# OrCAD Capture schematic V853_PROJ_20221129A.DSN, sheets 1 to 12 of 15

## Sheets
1 01 REVISION HISTORY: title: V853_PRO; rev: V1.0; company: 1; note: Block; note: 1; note: 1
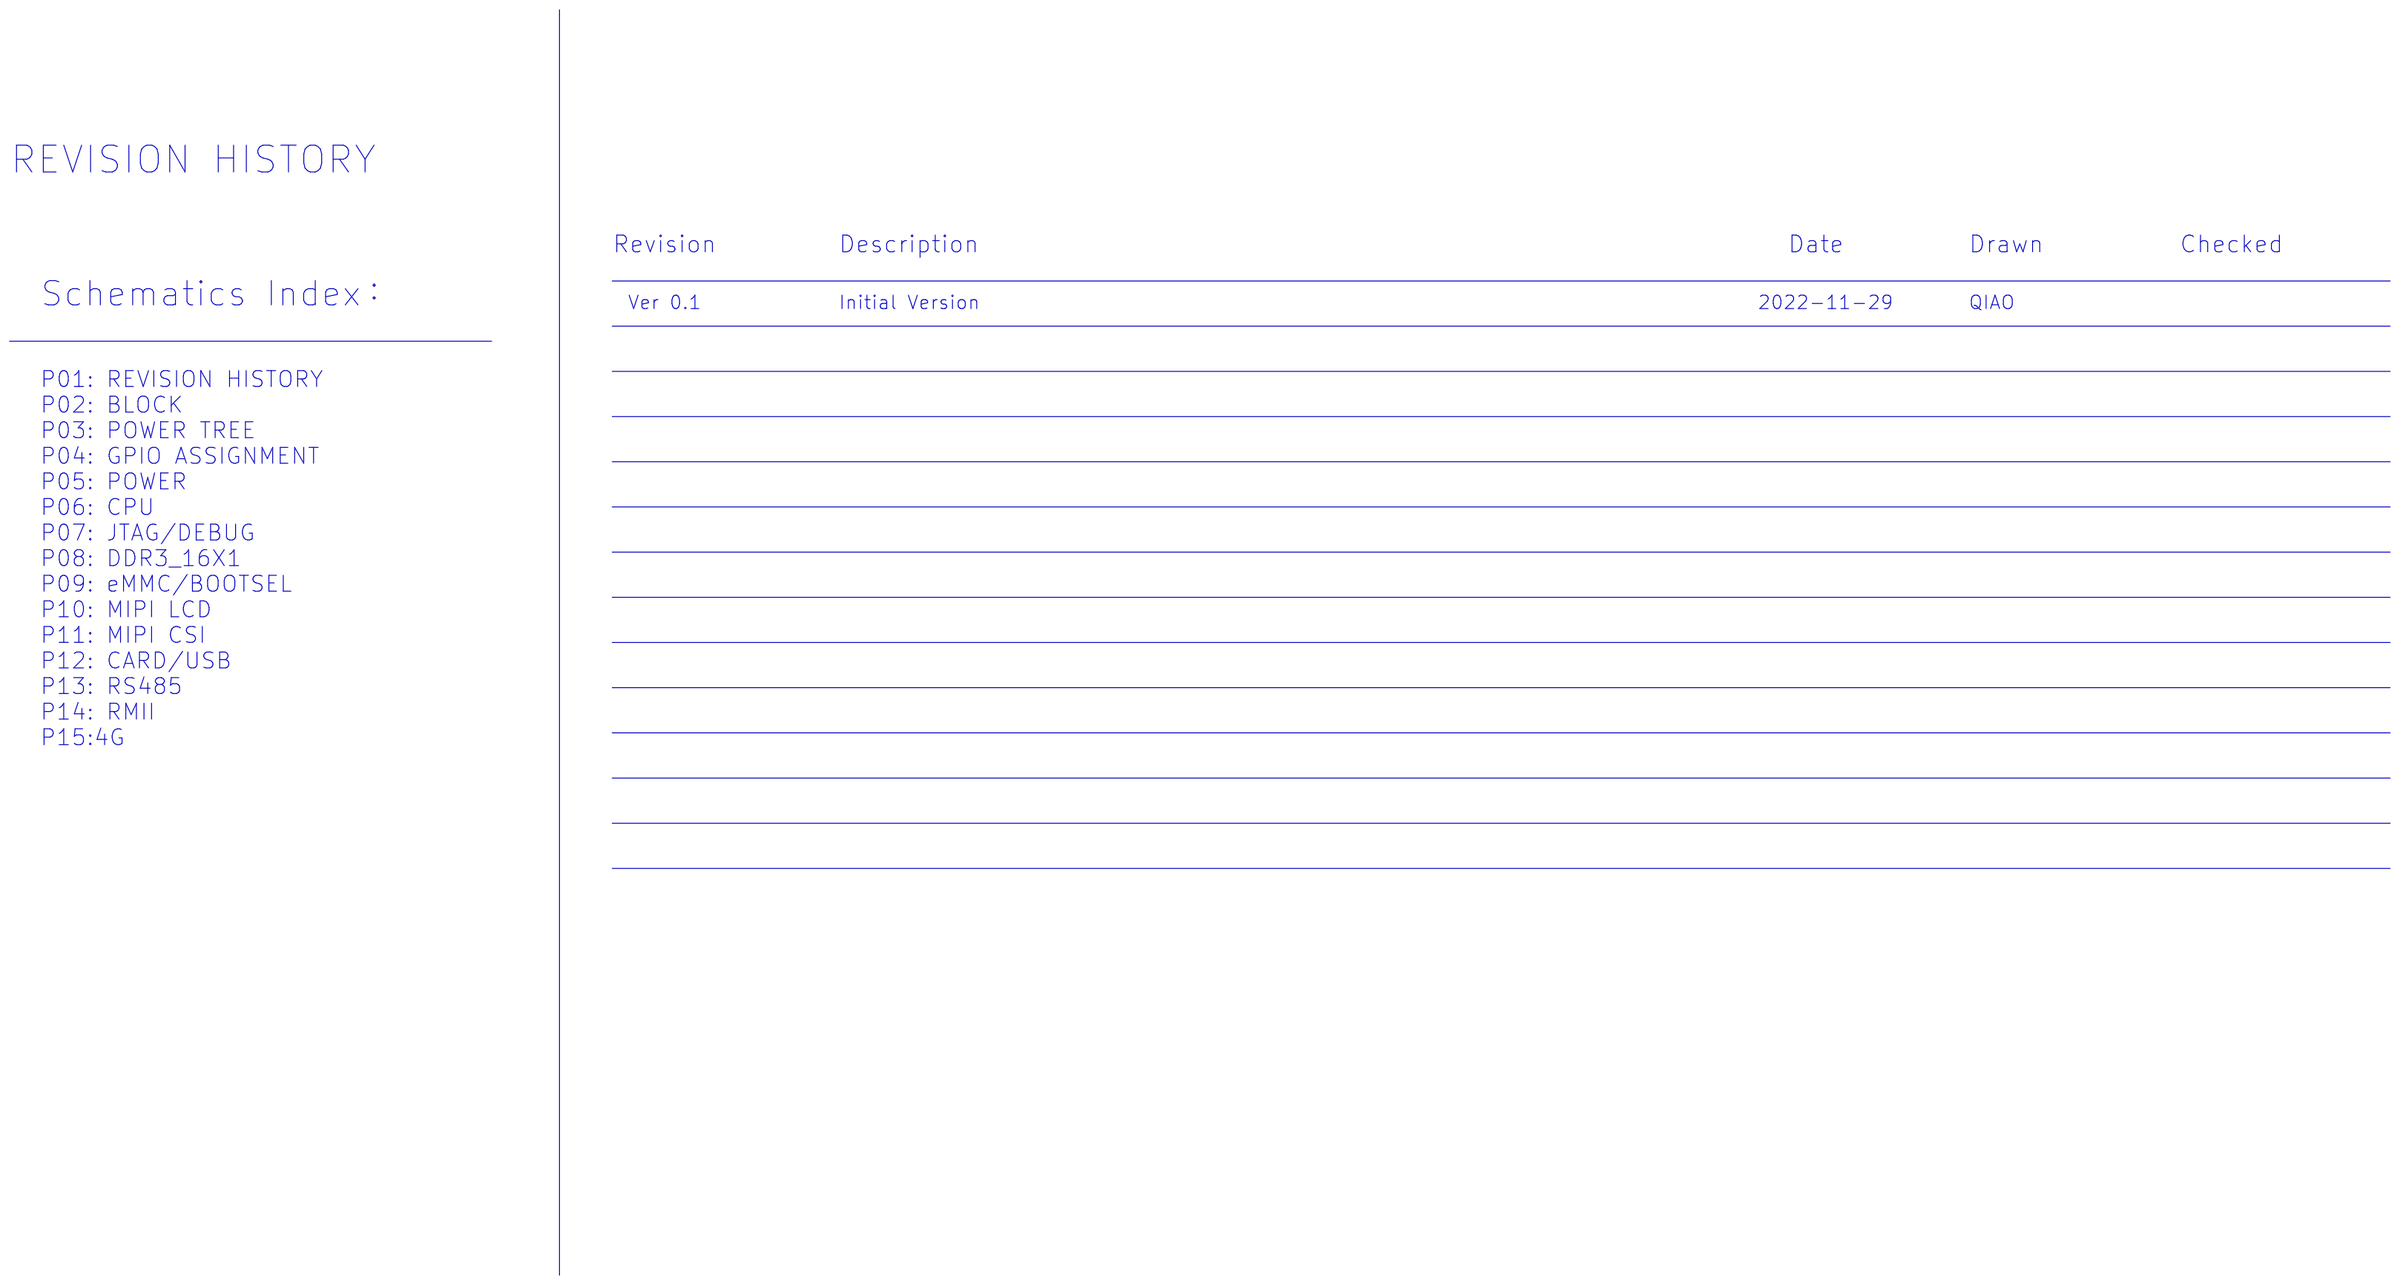
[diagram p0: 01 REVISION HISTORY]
2 02 BLOCK
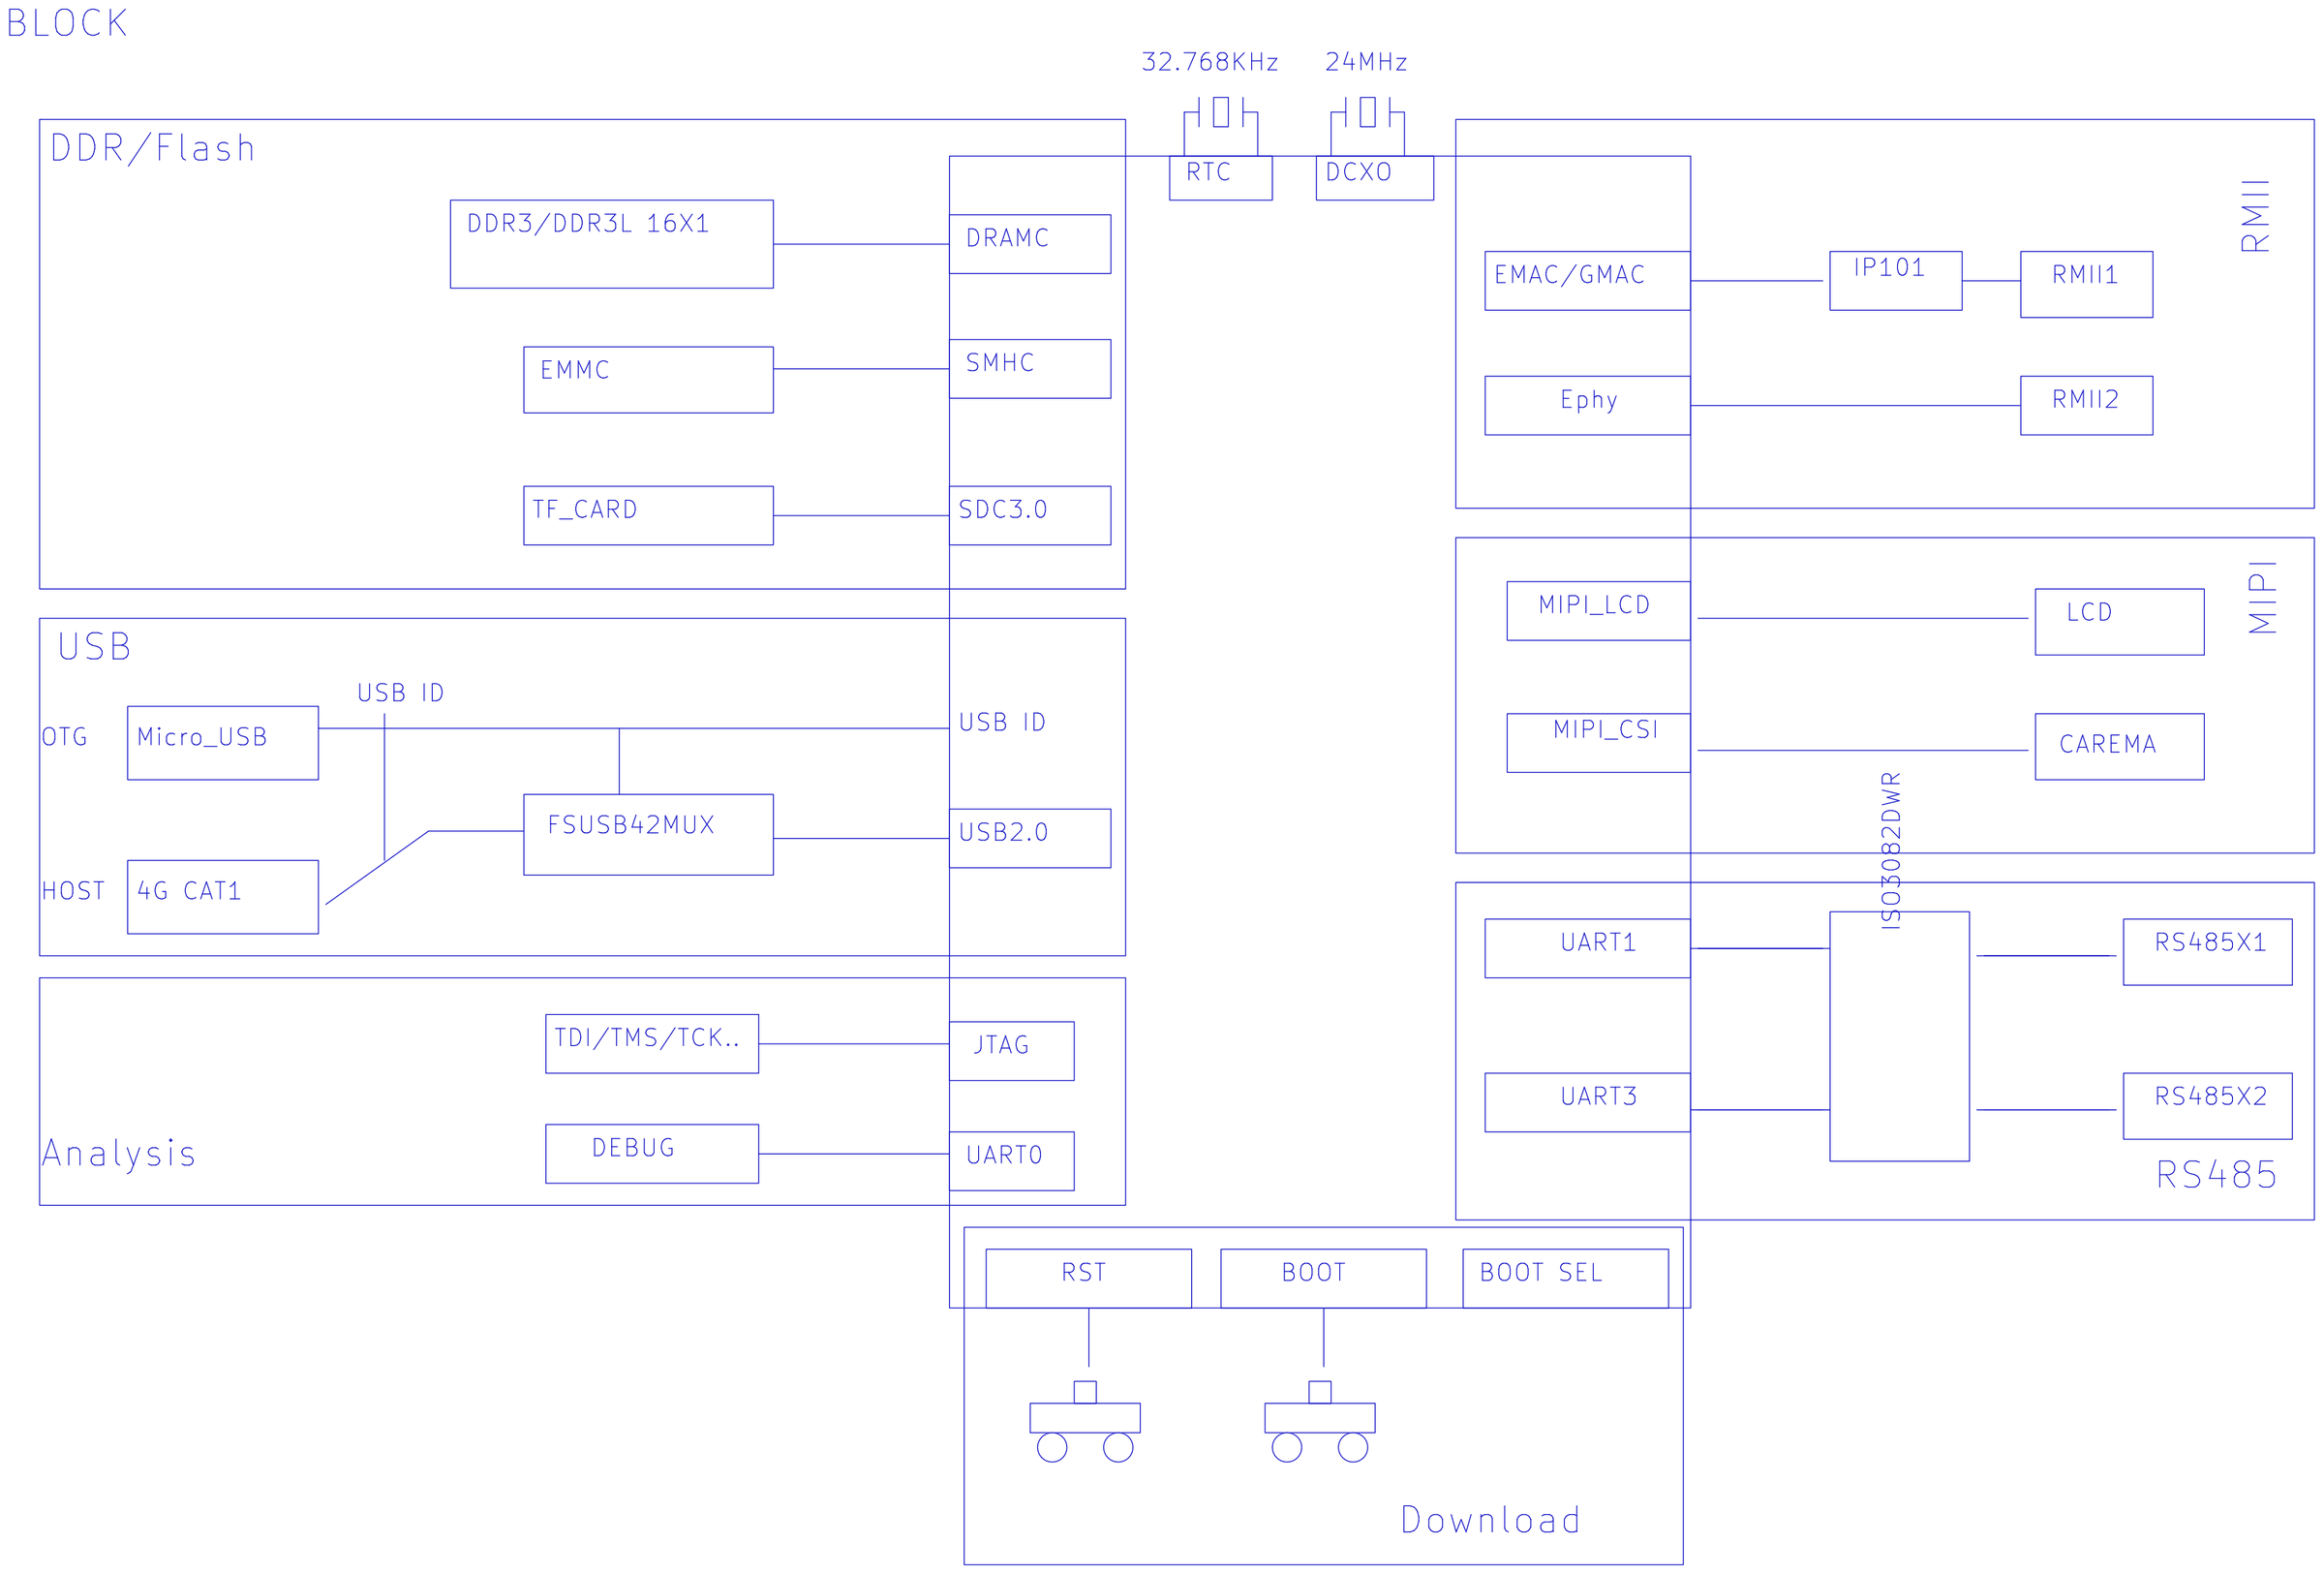
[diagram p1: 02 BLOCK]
3 03 POWER TREE: note: PWR TREE
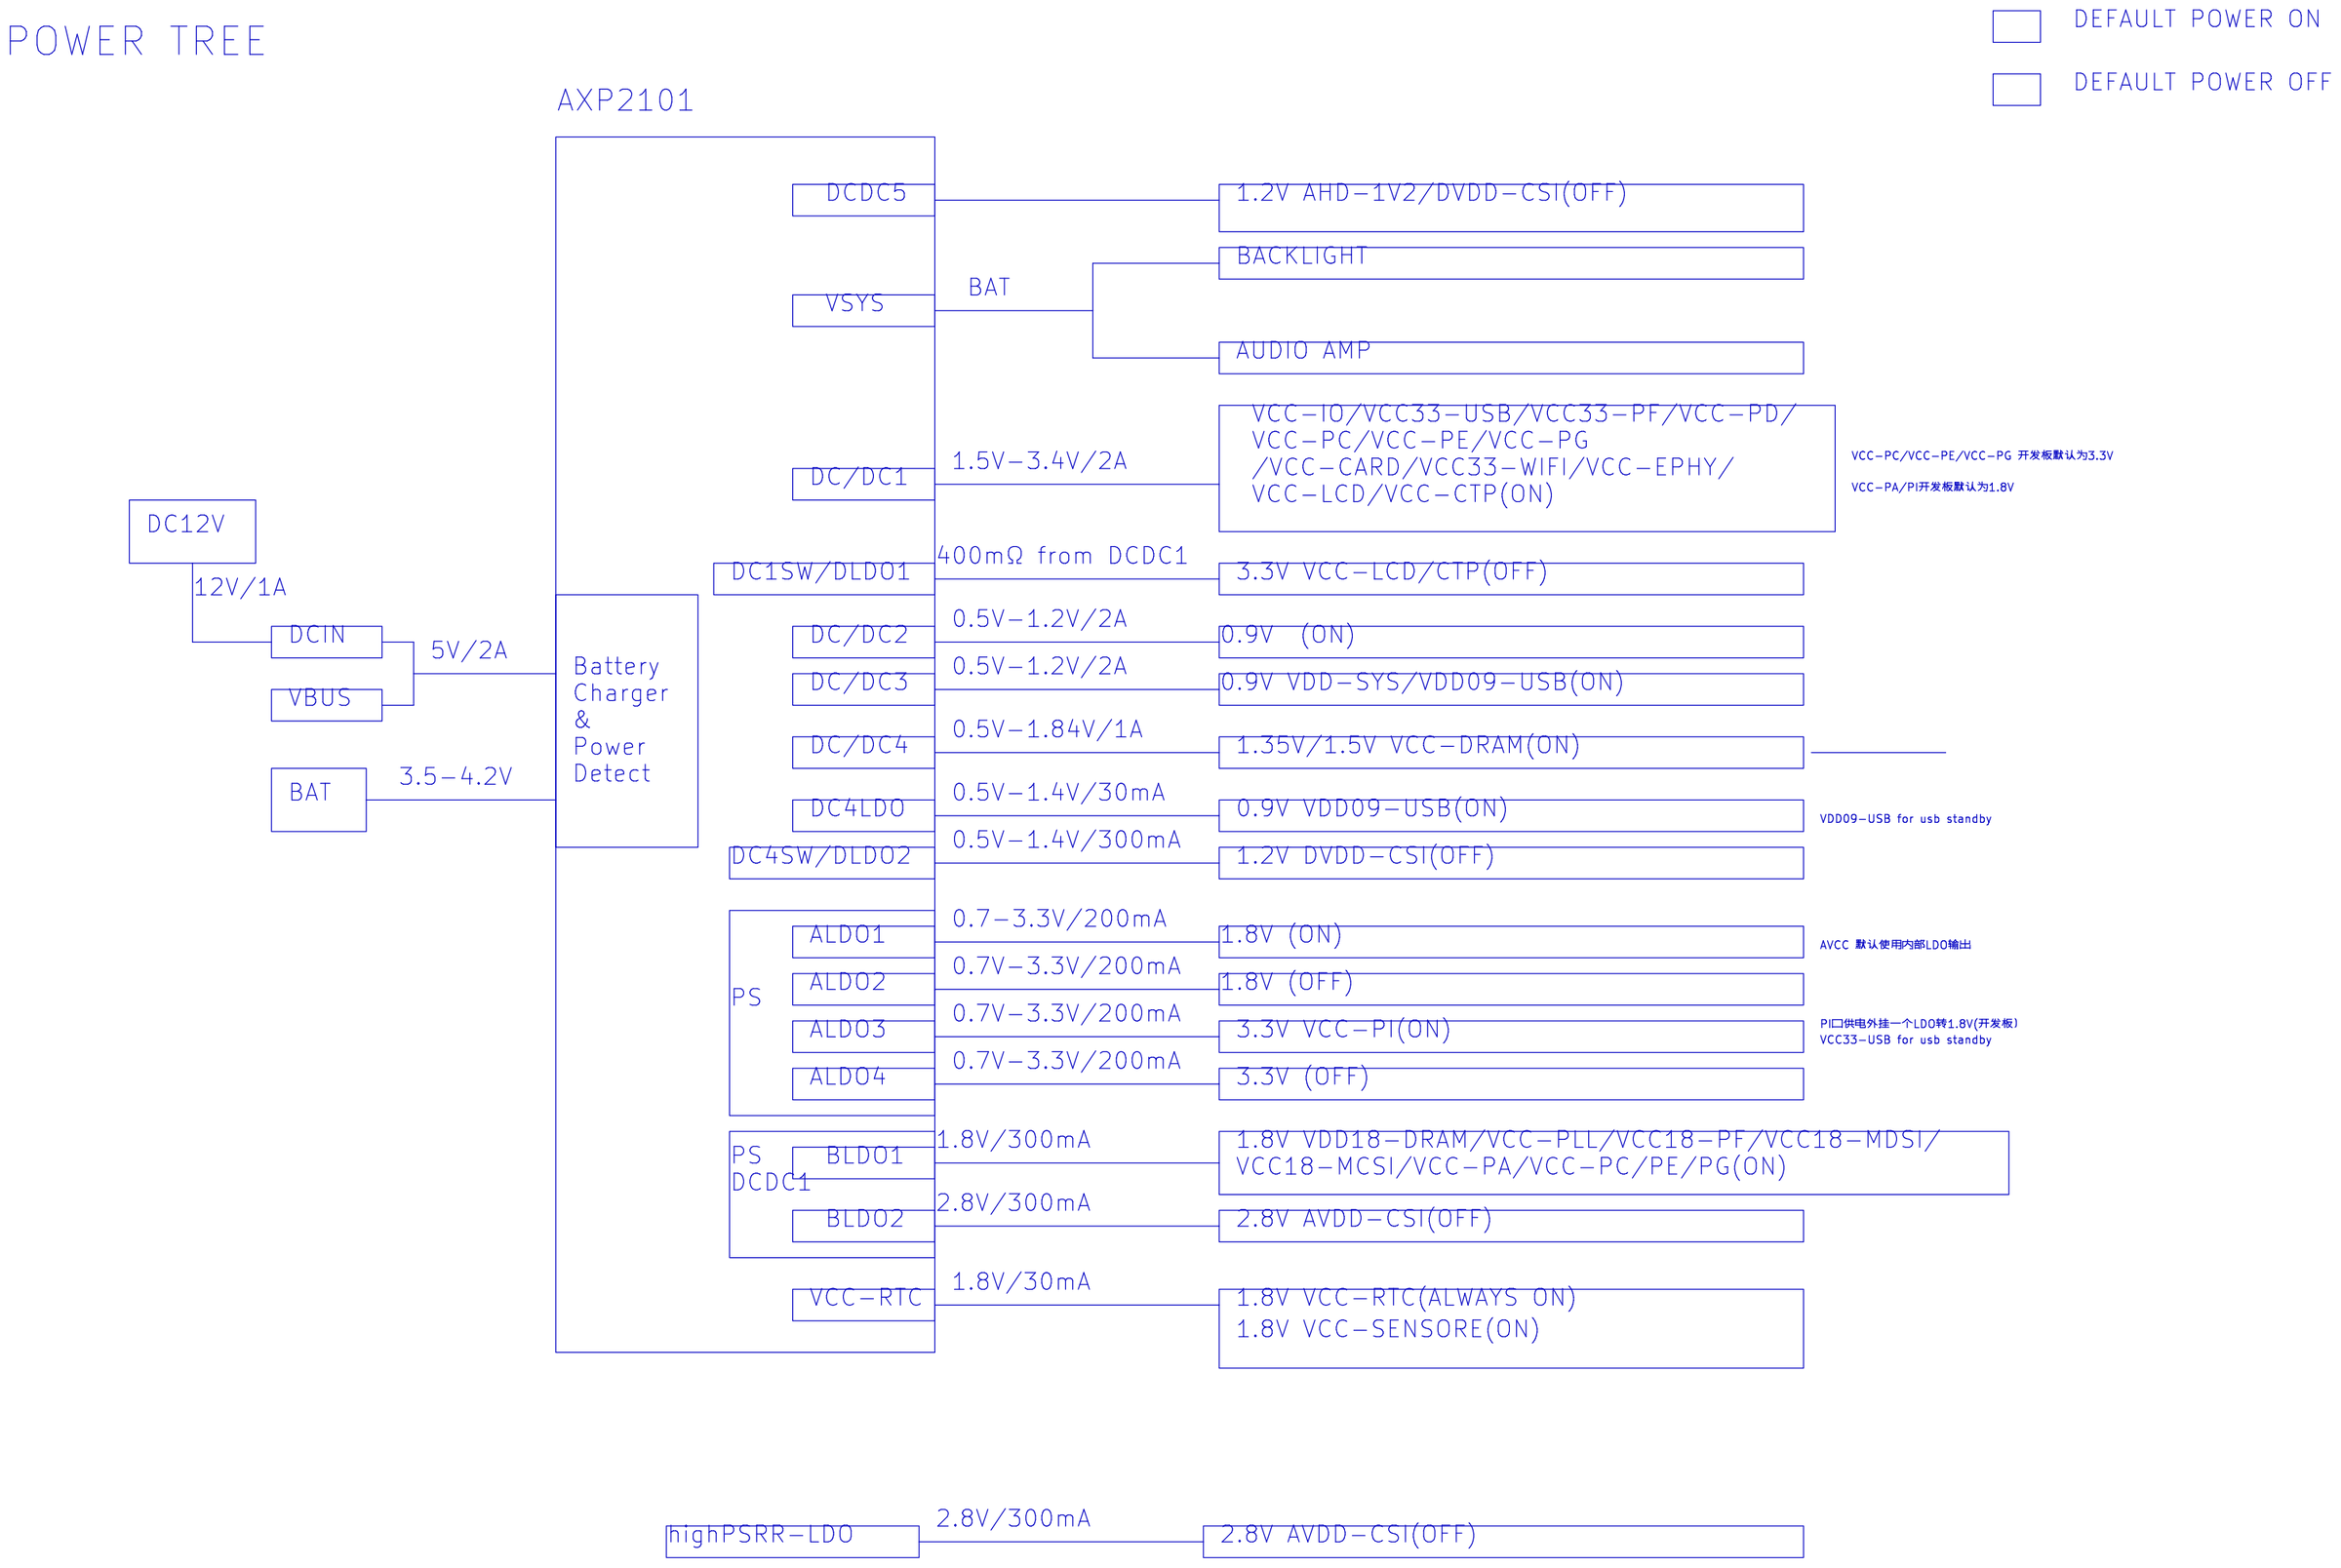
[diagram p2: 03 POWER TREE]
4 04 GPIO ASSIGNMENT: note: GPIO_CTRL
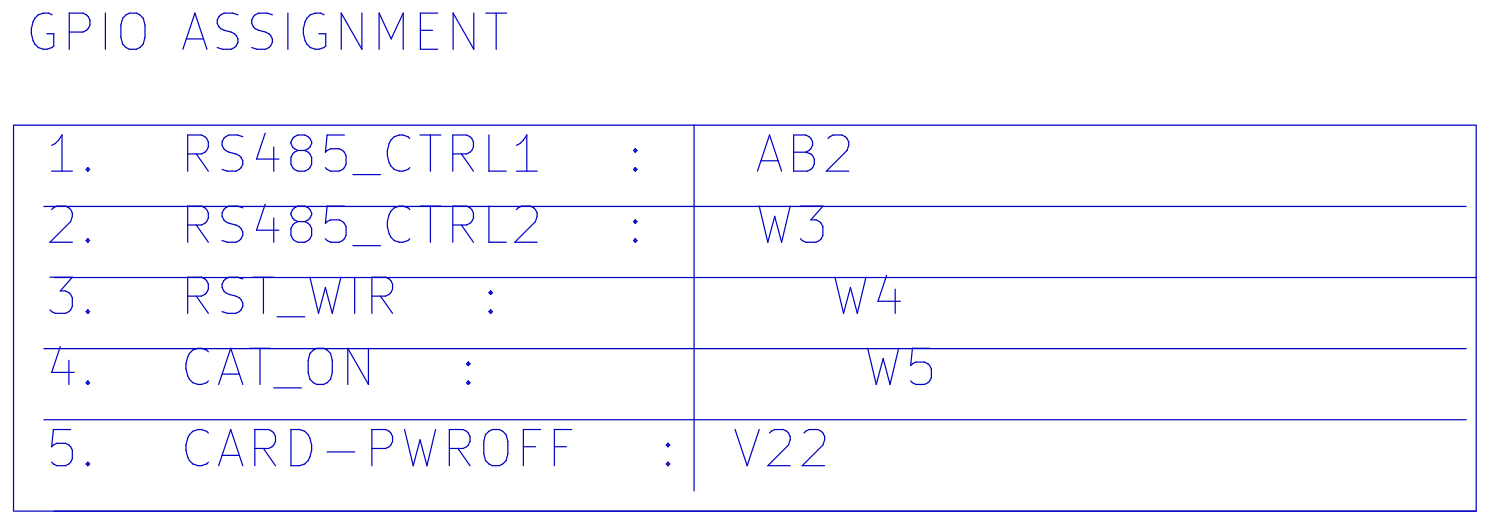
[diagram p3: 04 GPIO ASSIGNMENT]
5 05 POWER: size A2; note: PWR
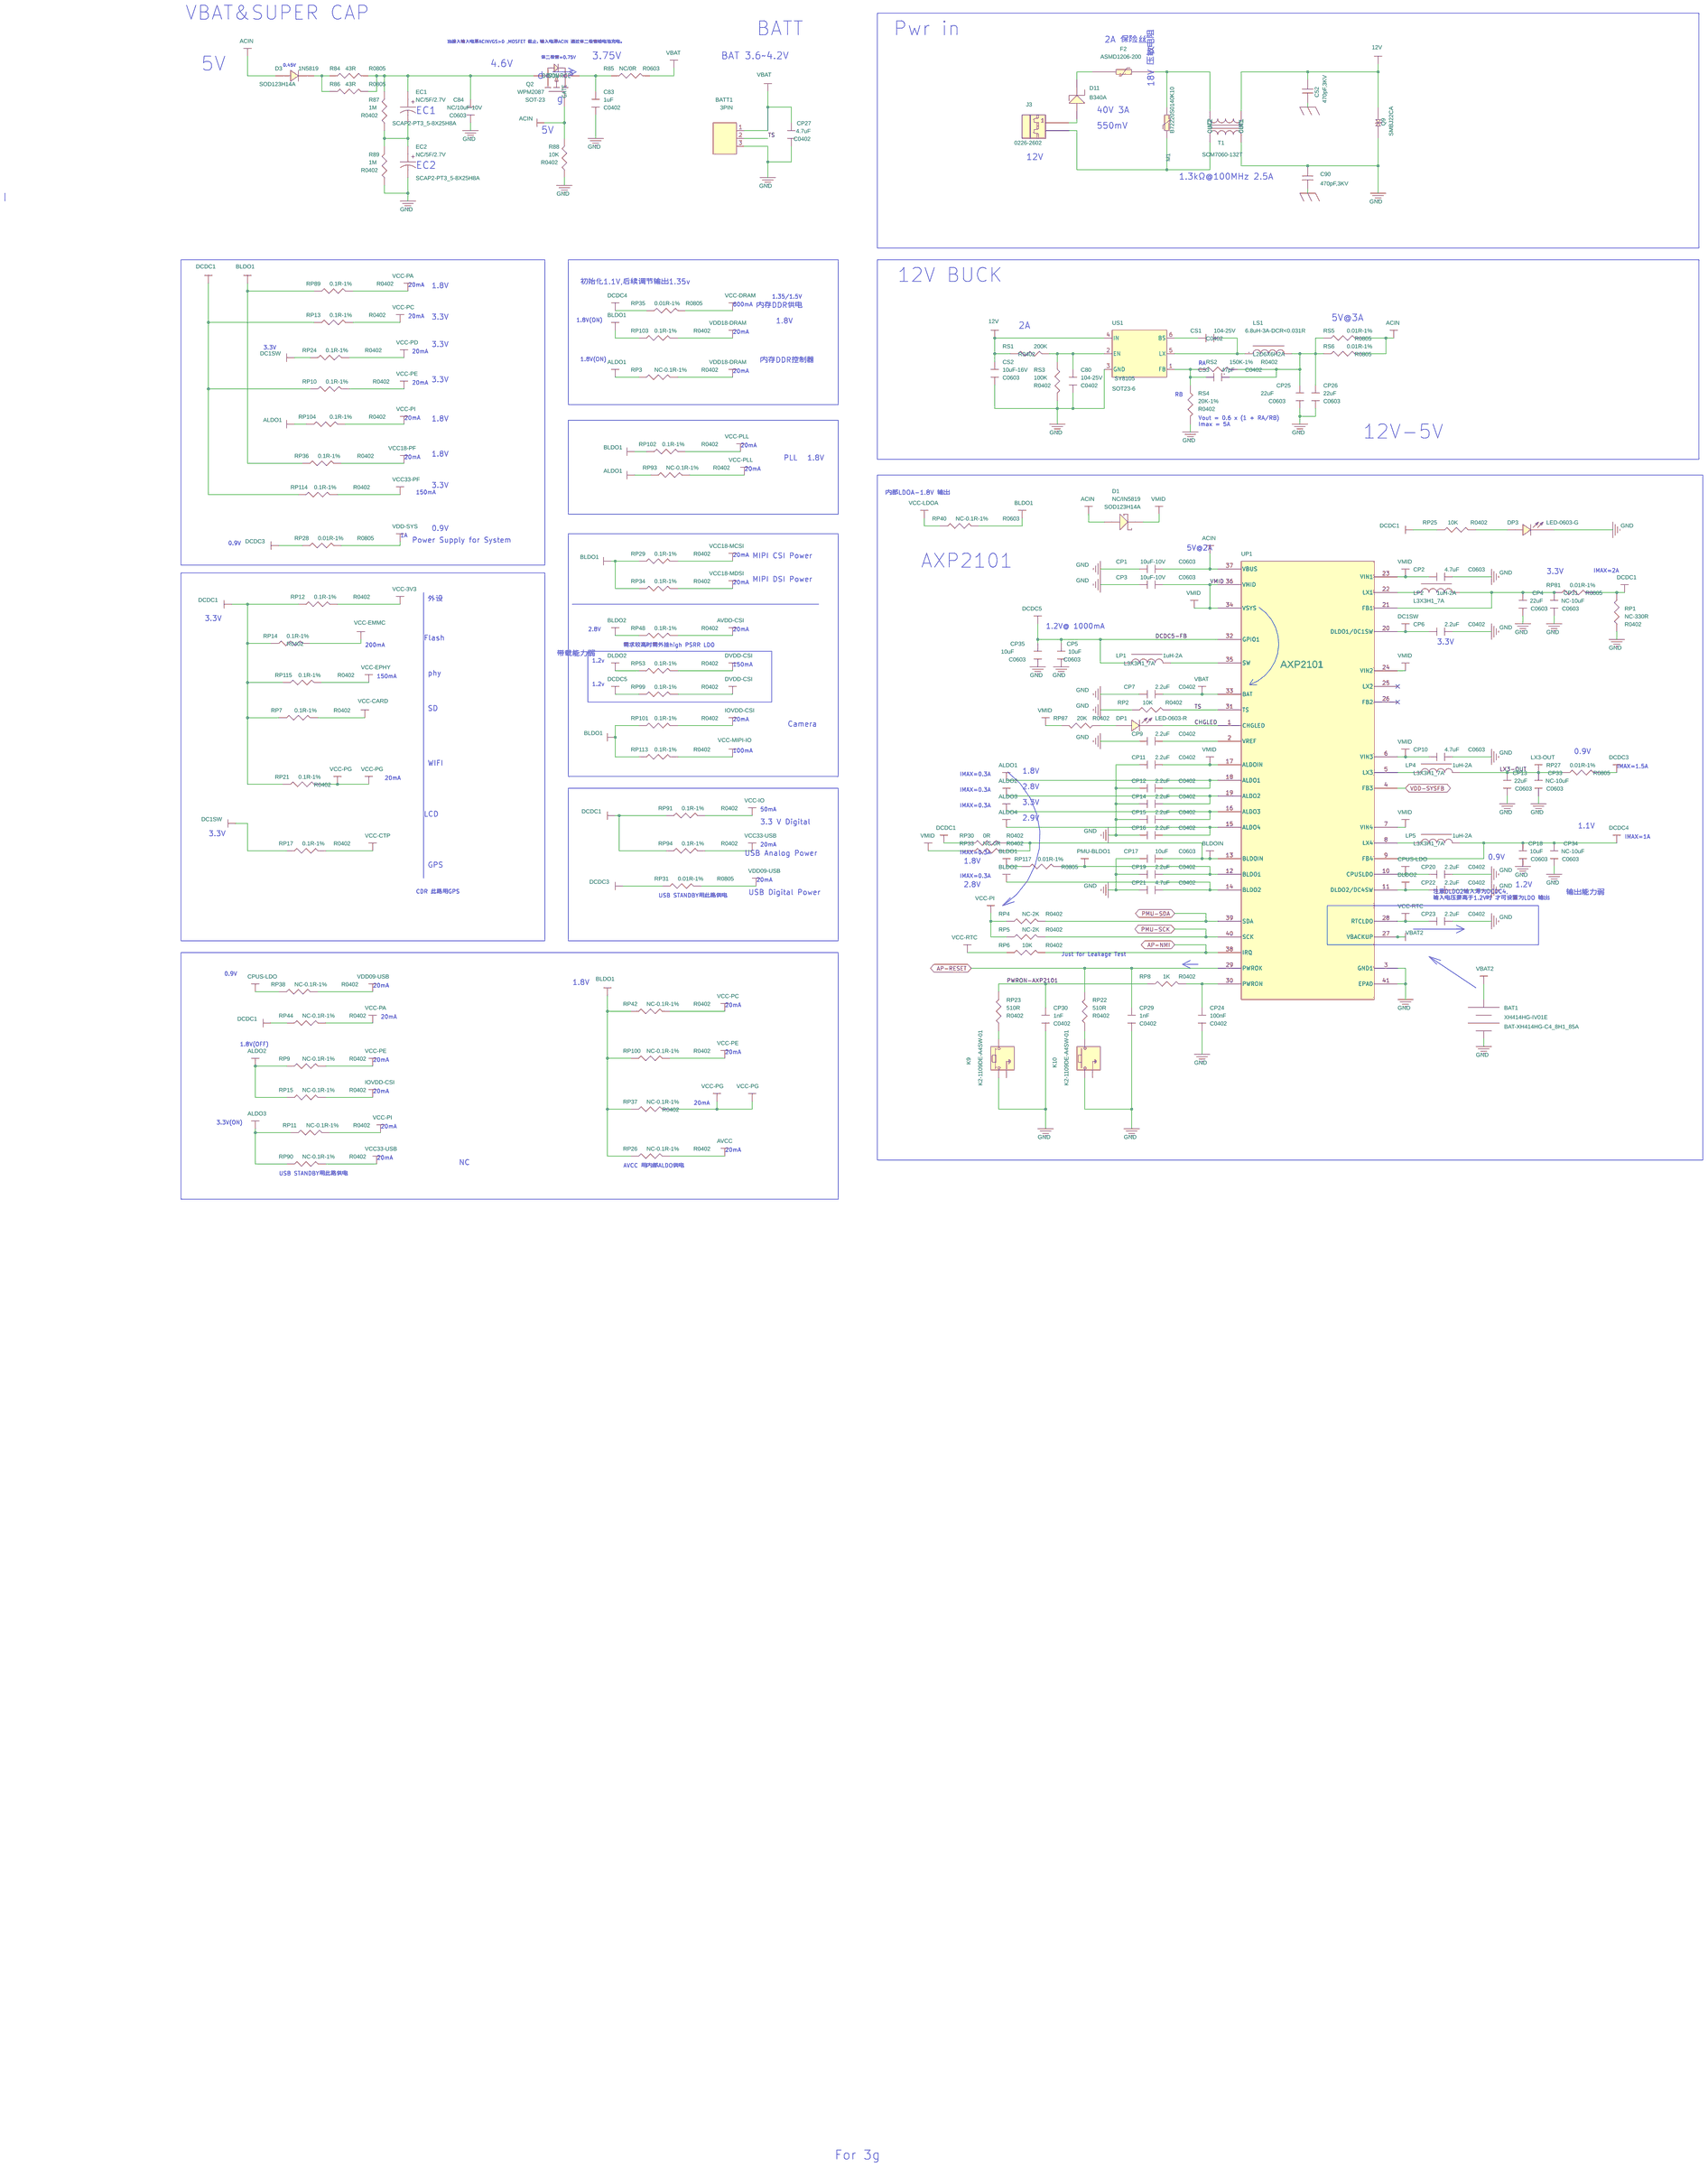
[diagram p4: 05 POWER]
6 06 CPU: size A3; note: MPU
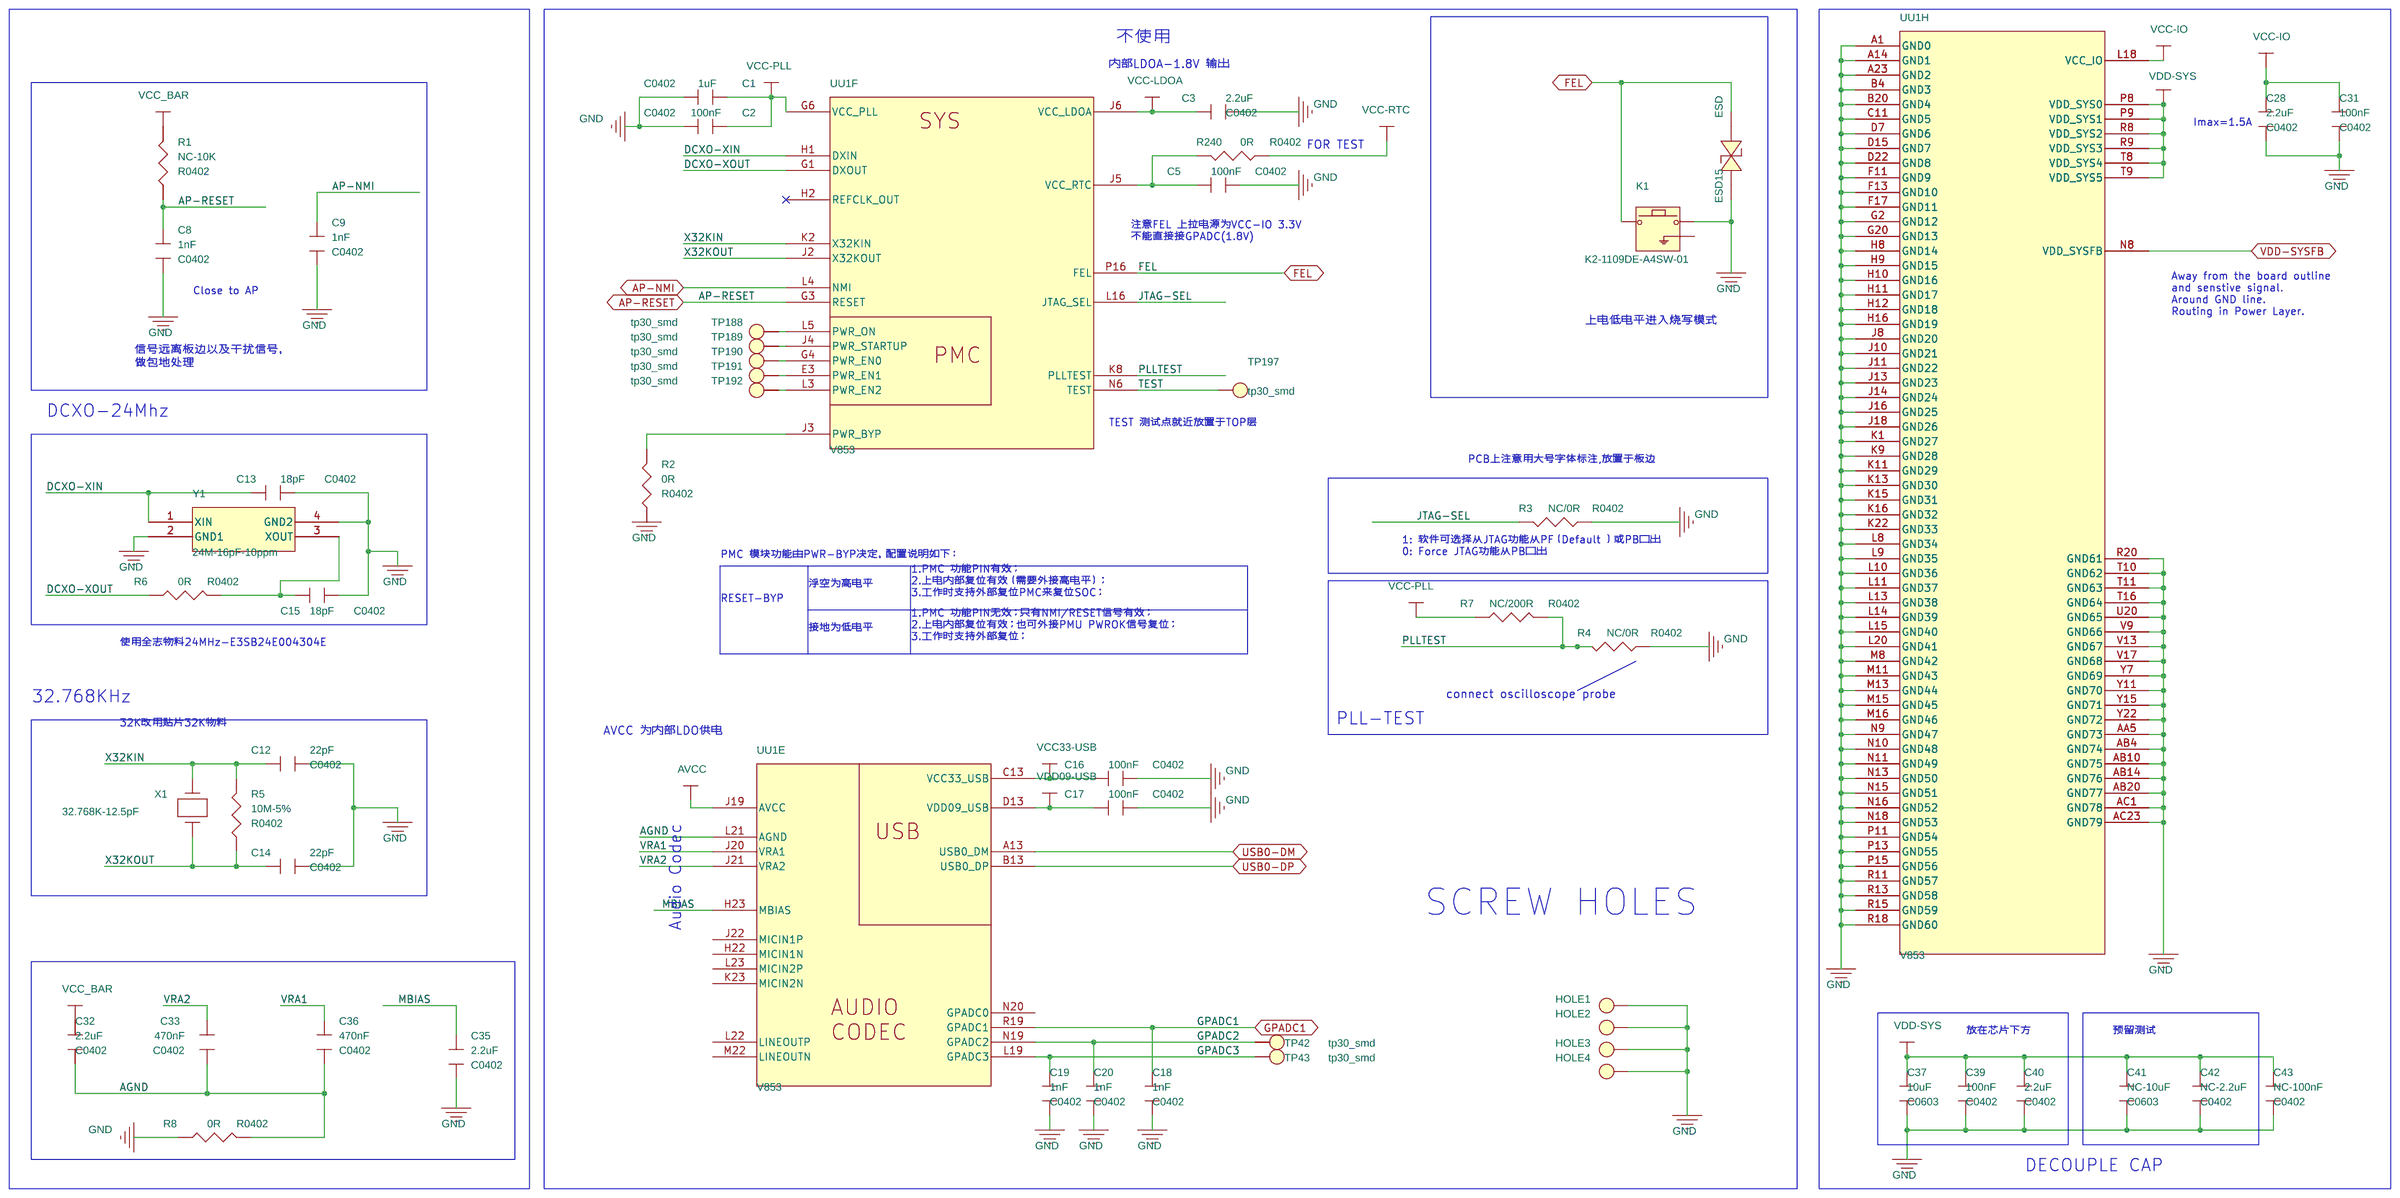
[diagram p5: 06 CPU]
7 08 DDR3_16X1: size A3; note: DDR
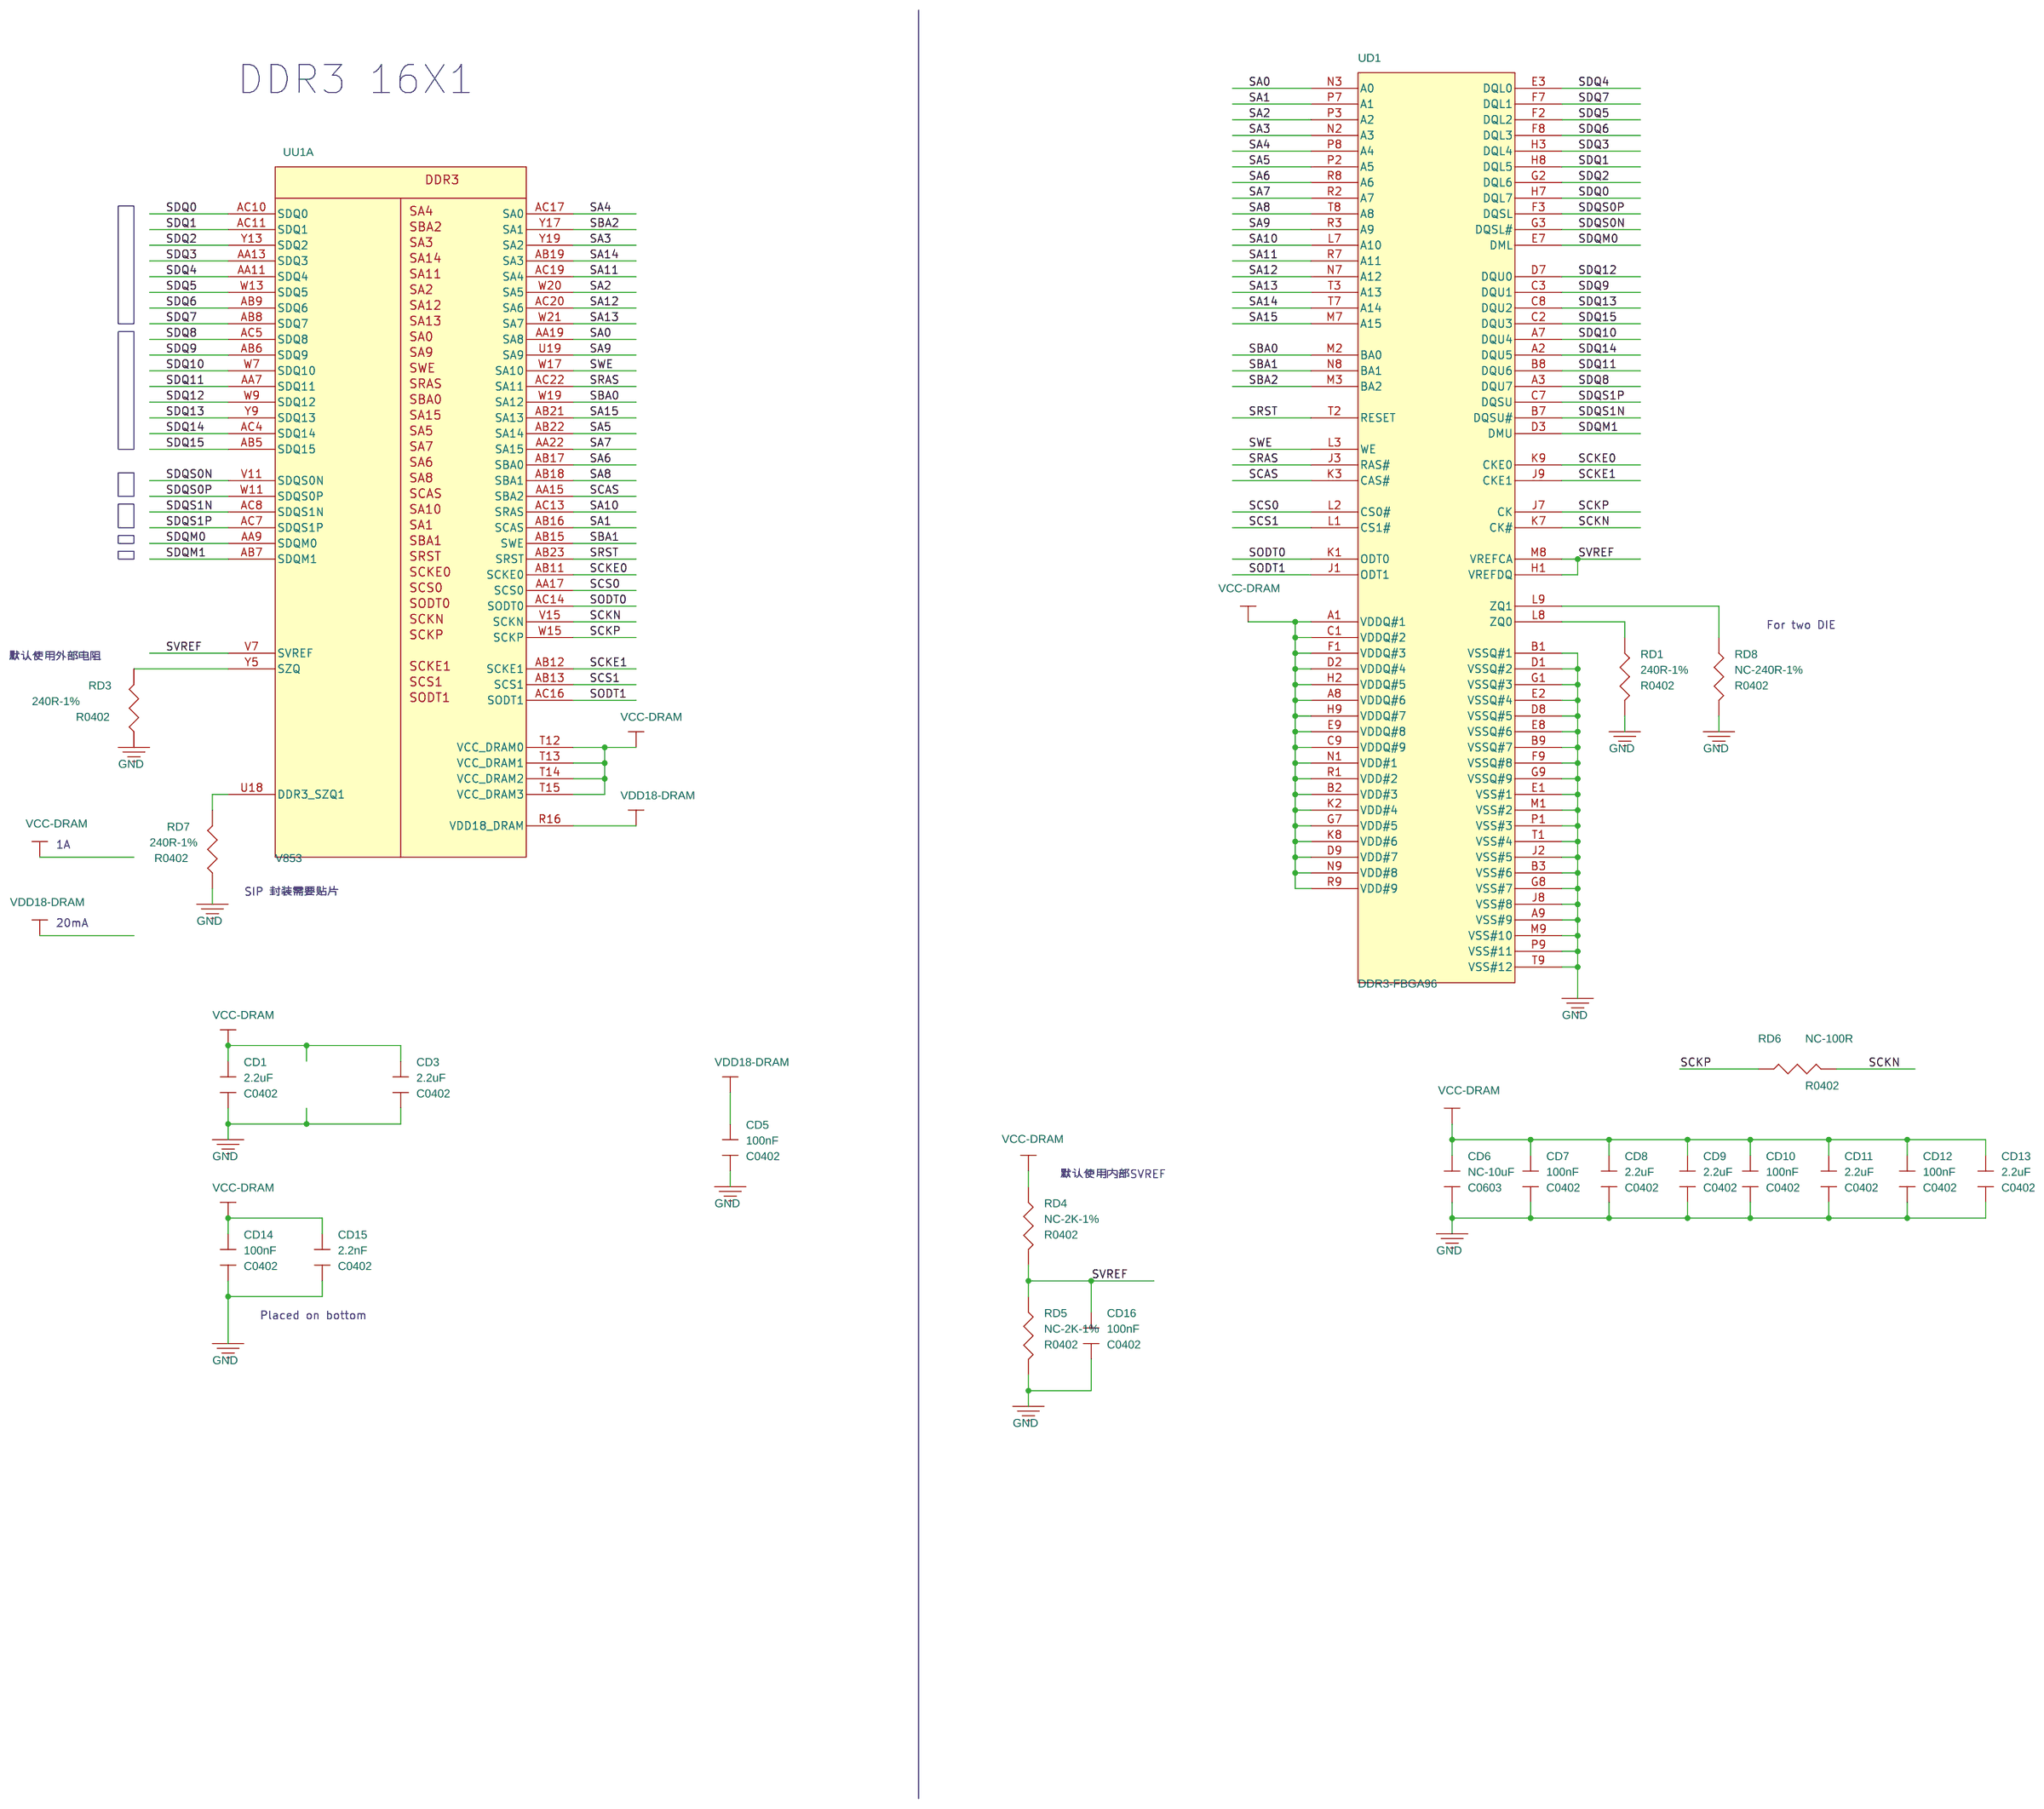
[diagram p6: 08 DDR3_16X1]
8 10 MIPI_LCD: size A3; note: LCD
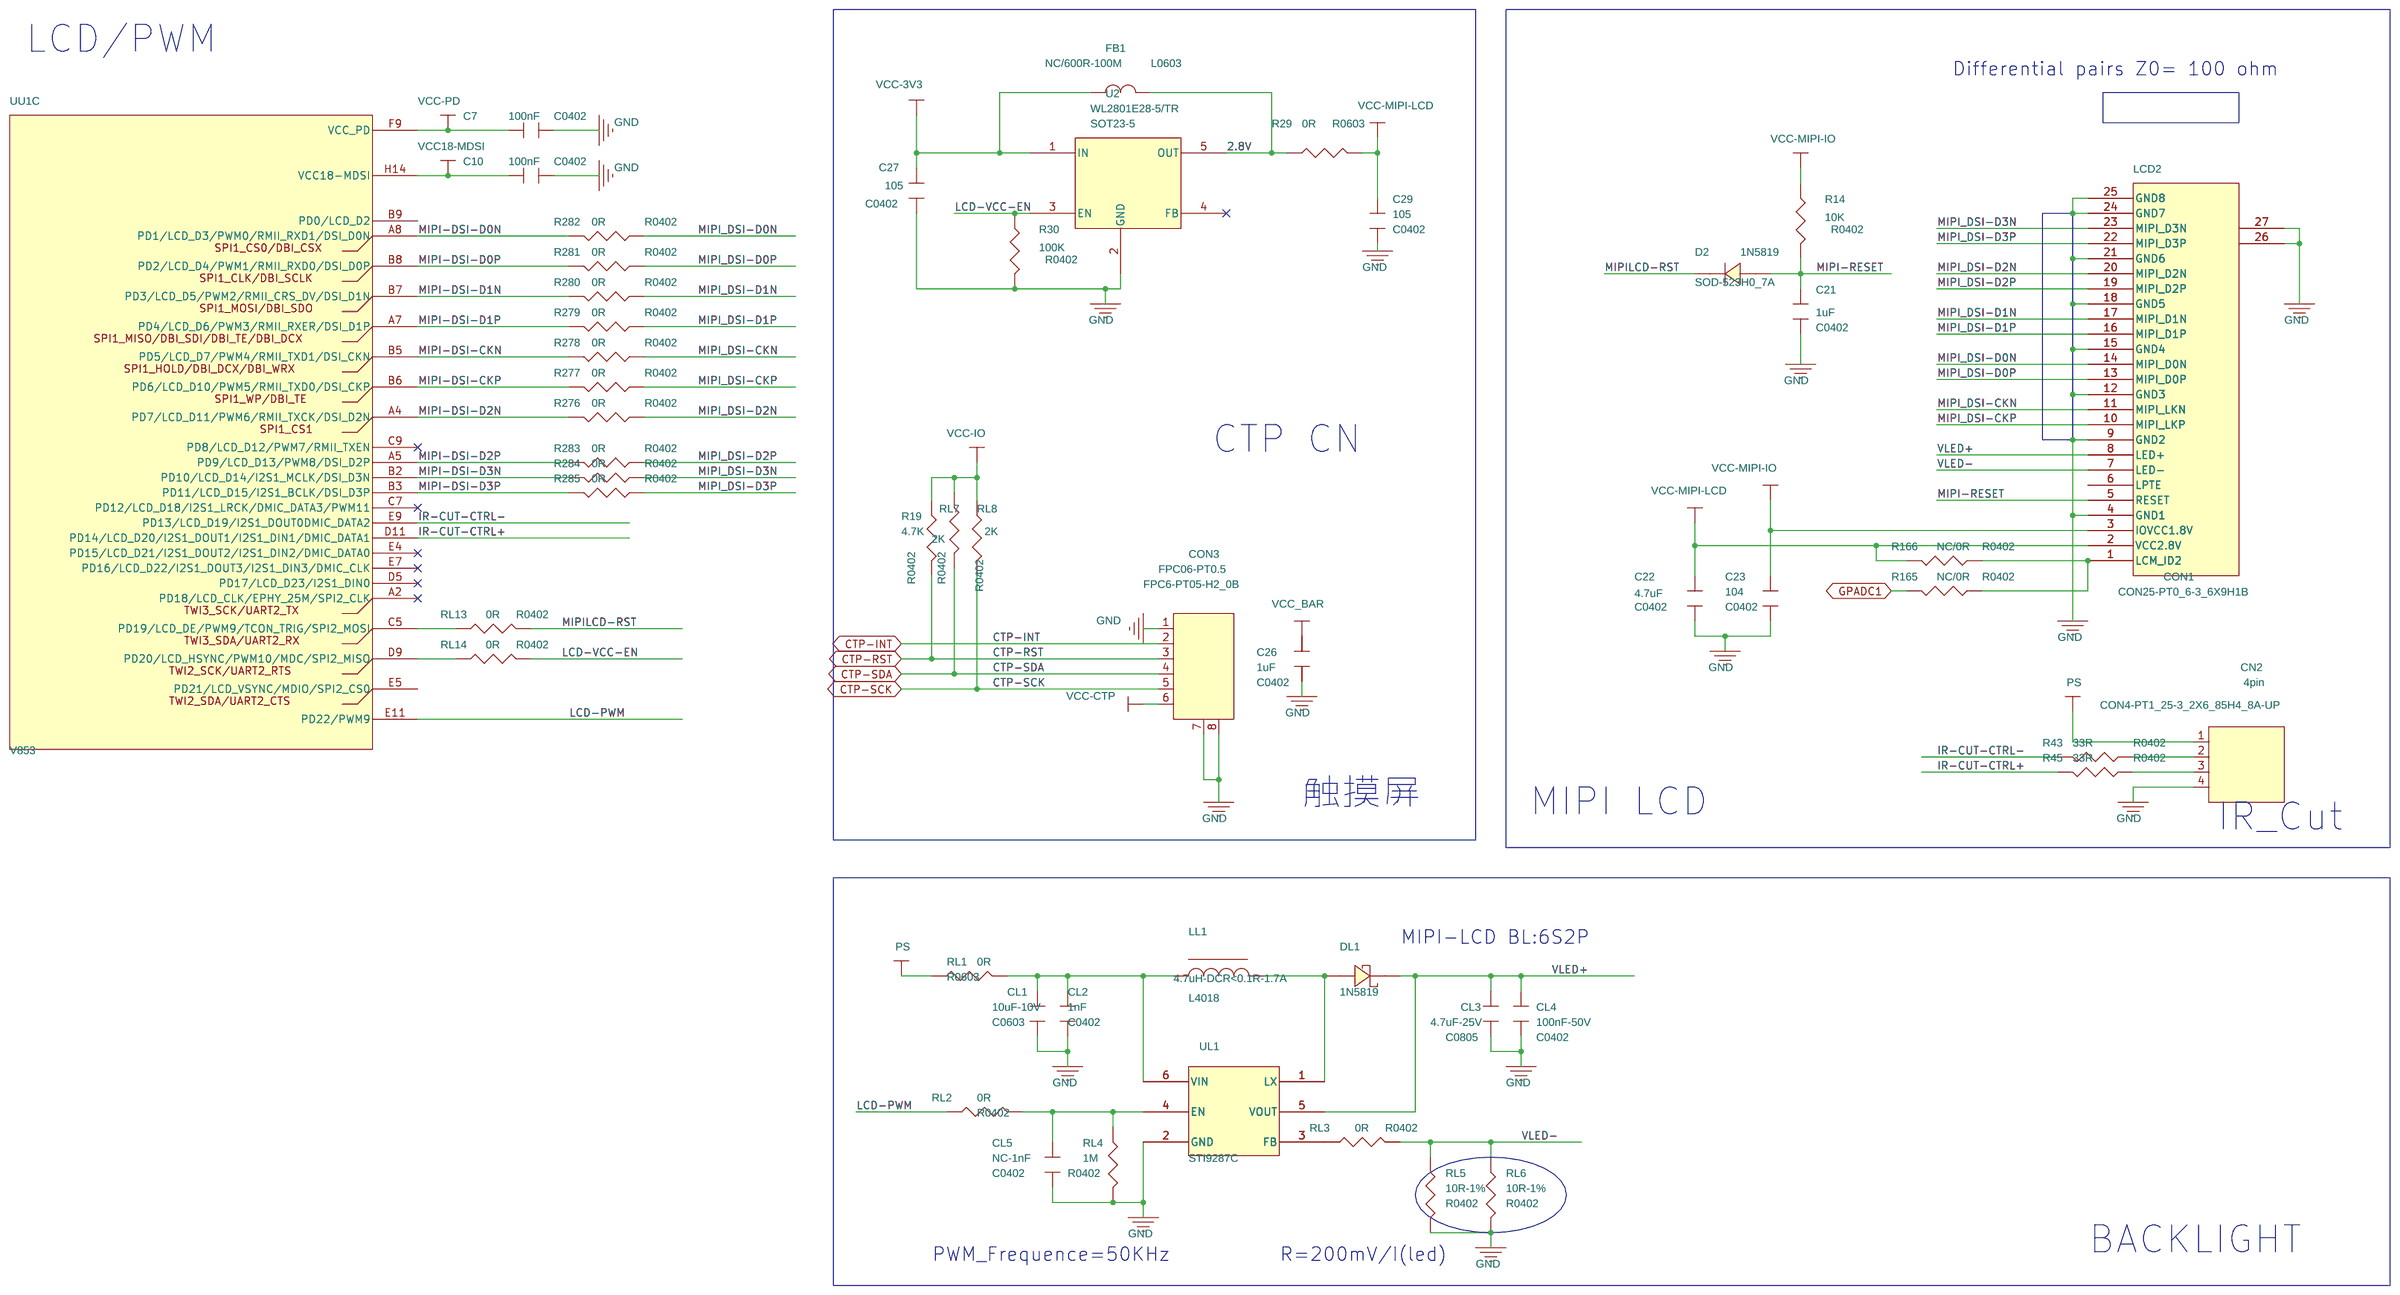
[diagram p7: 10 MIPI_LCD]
9 11 MIPI CSI: size A3; note: MIPI_Carema
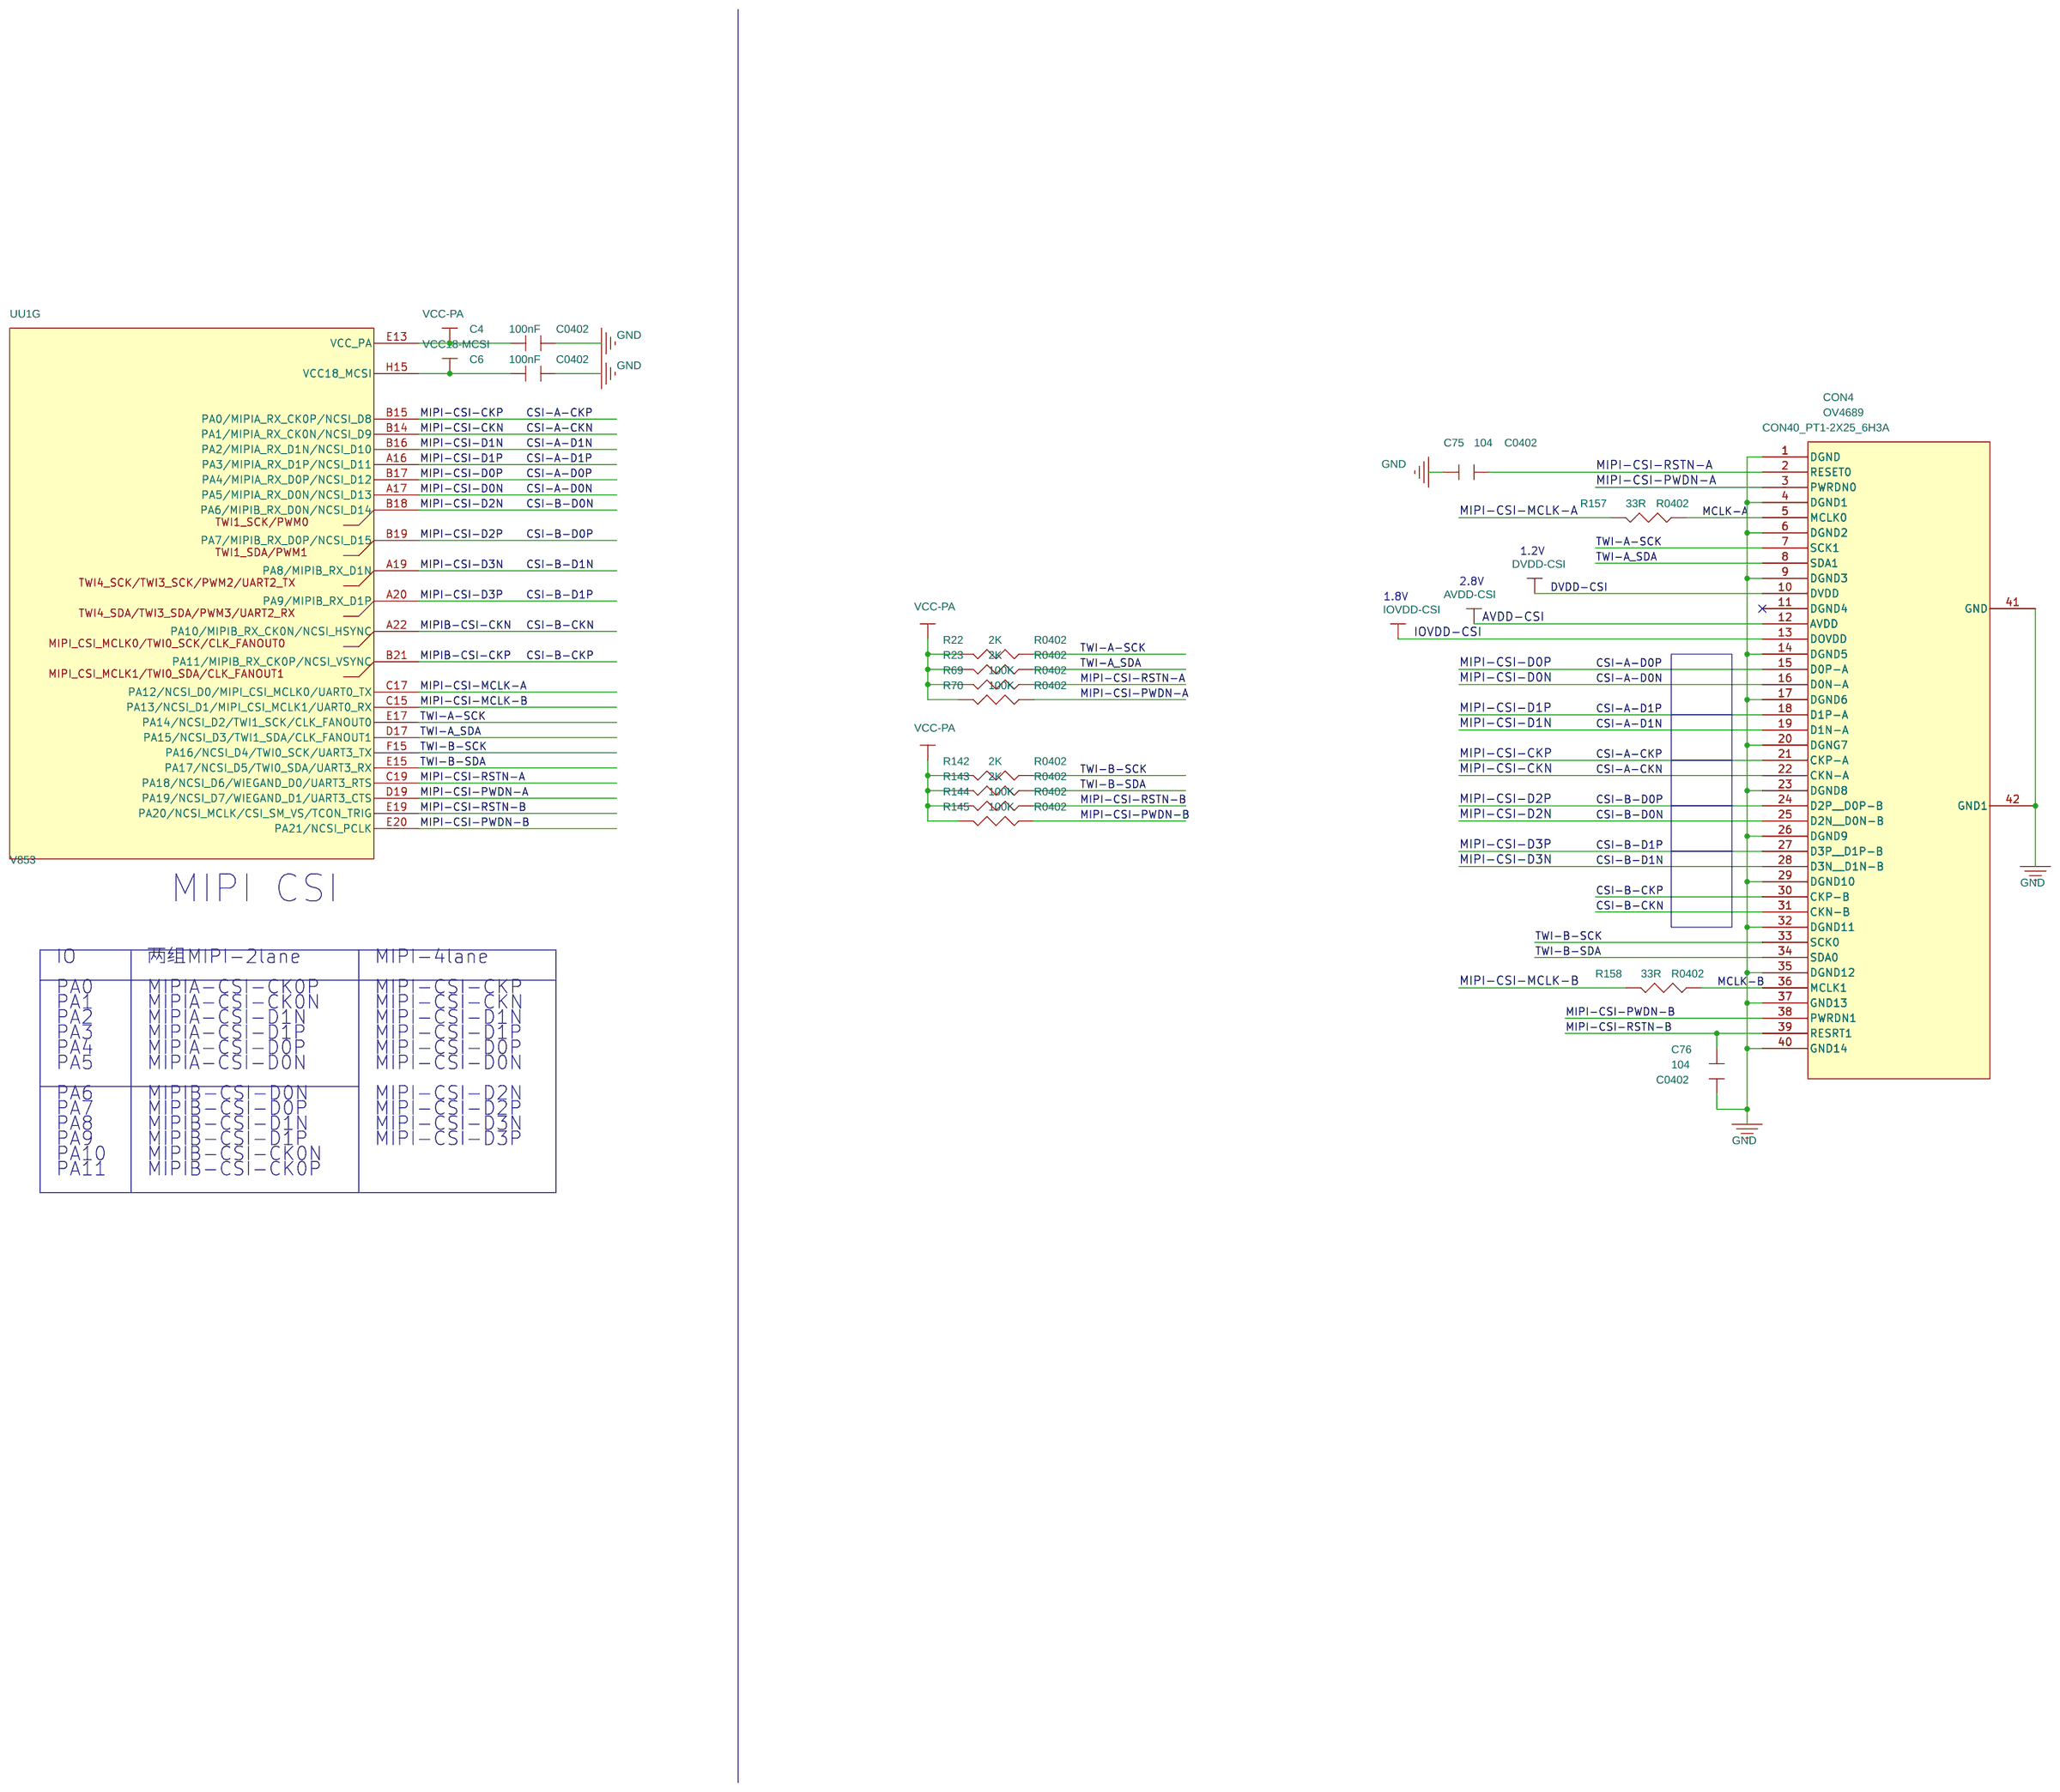
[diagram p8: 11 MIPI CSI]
10 13 RS485: size A3; note: rs485_ISO
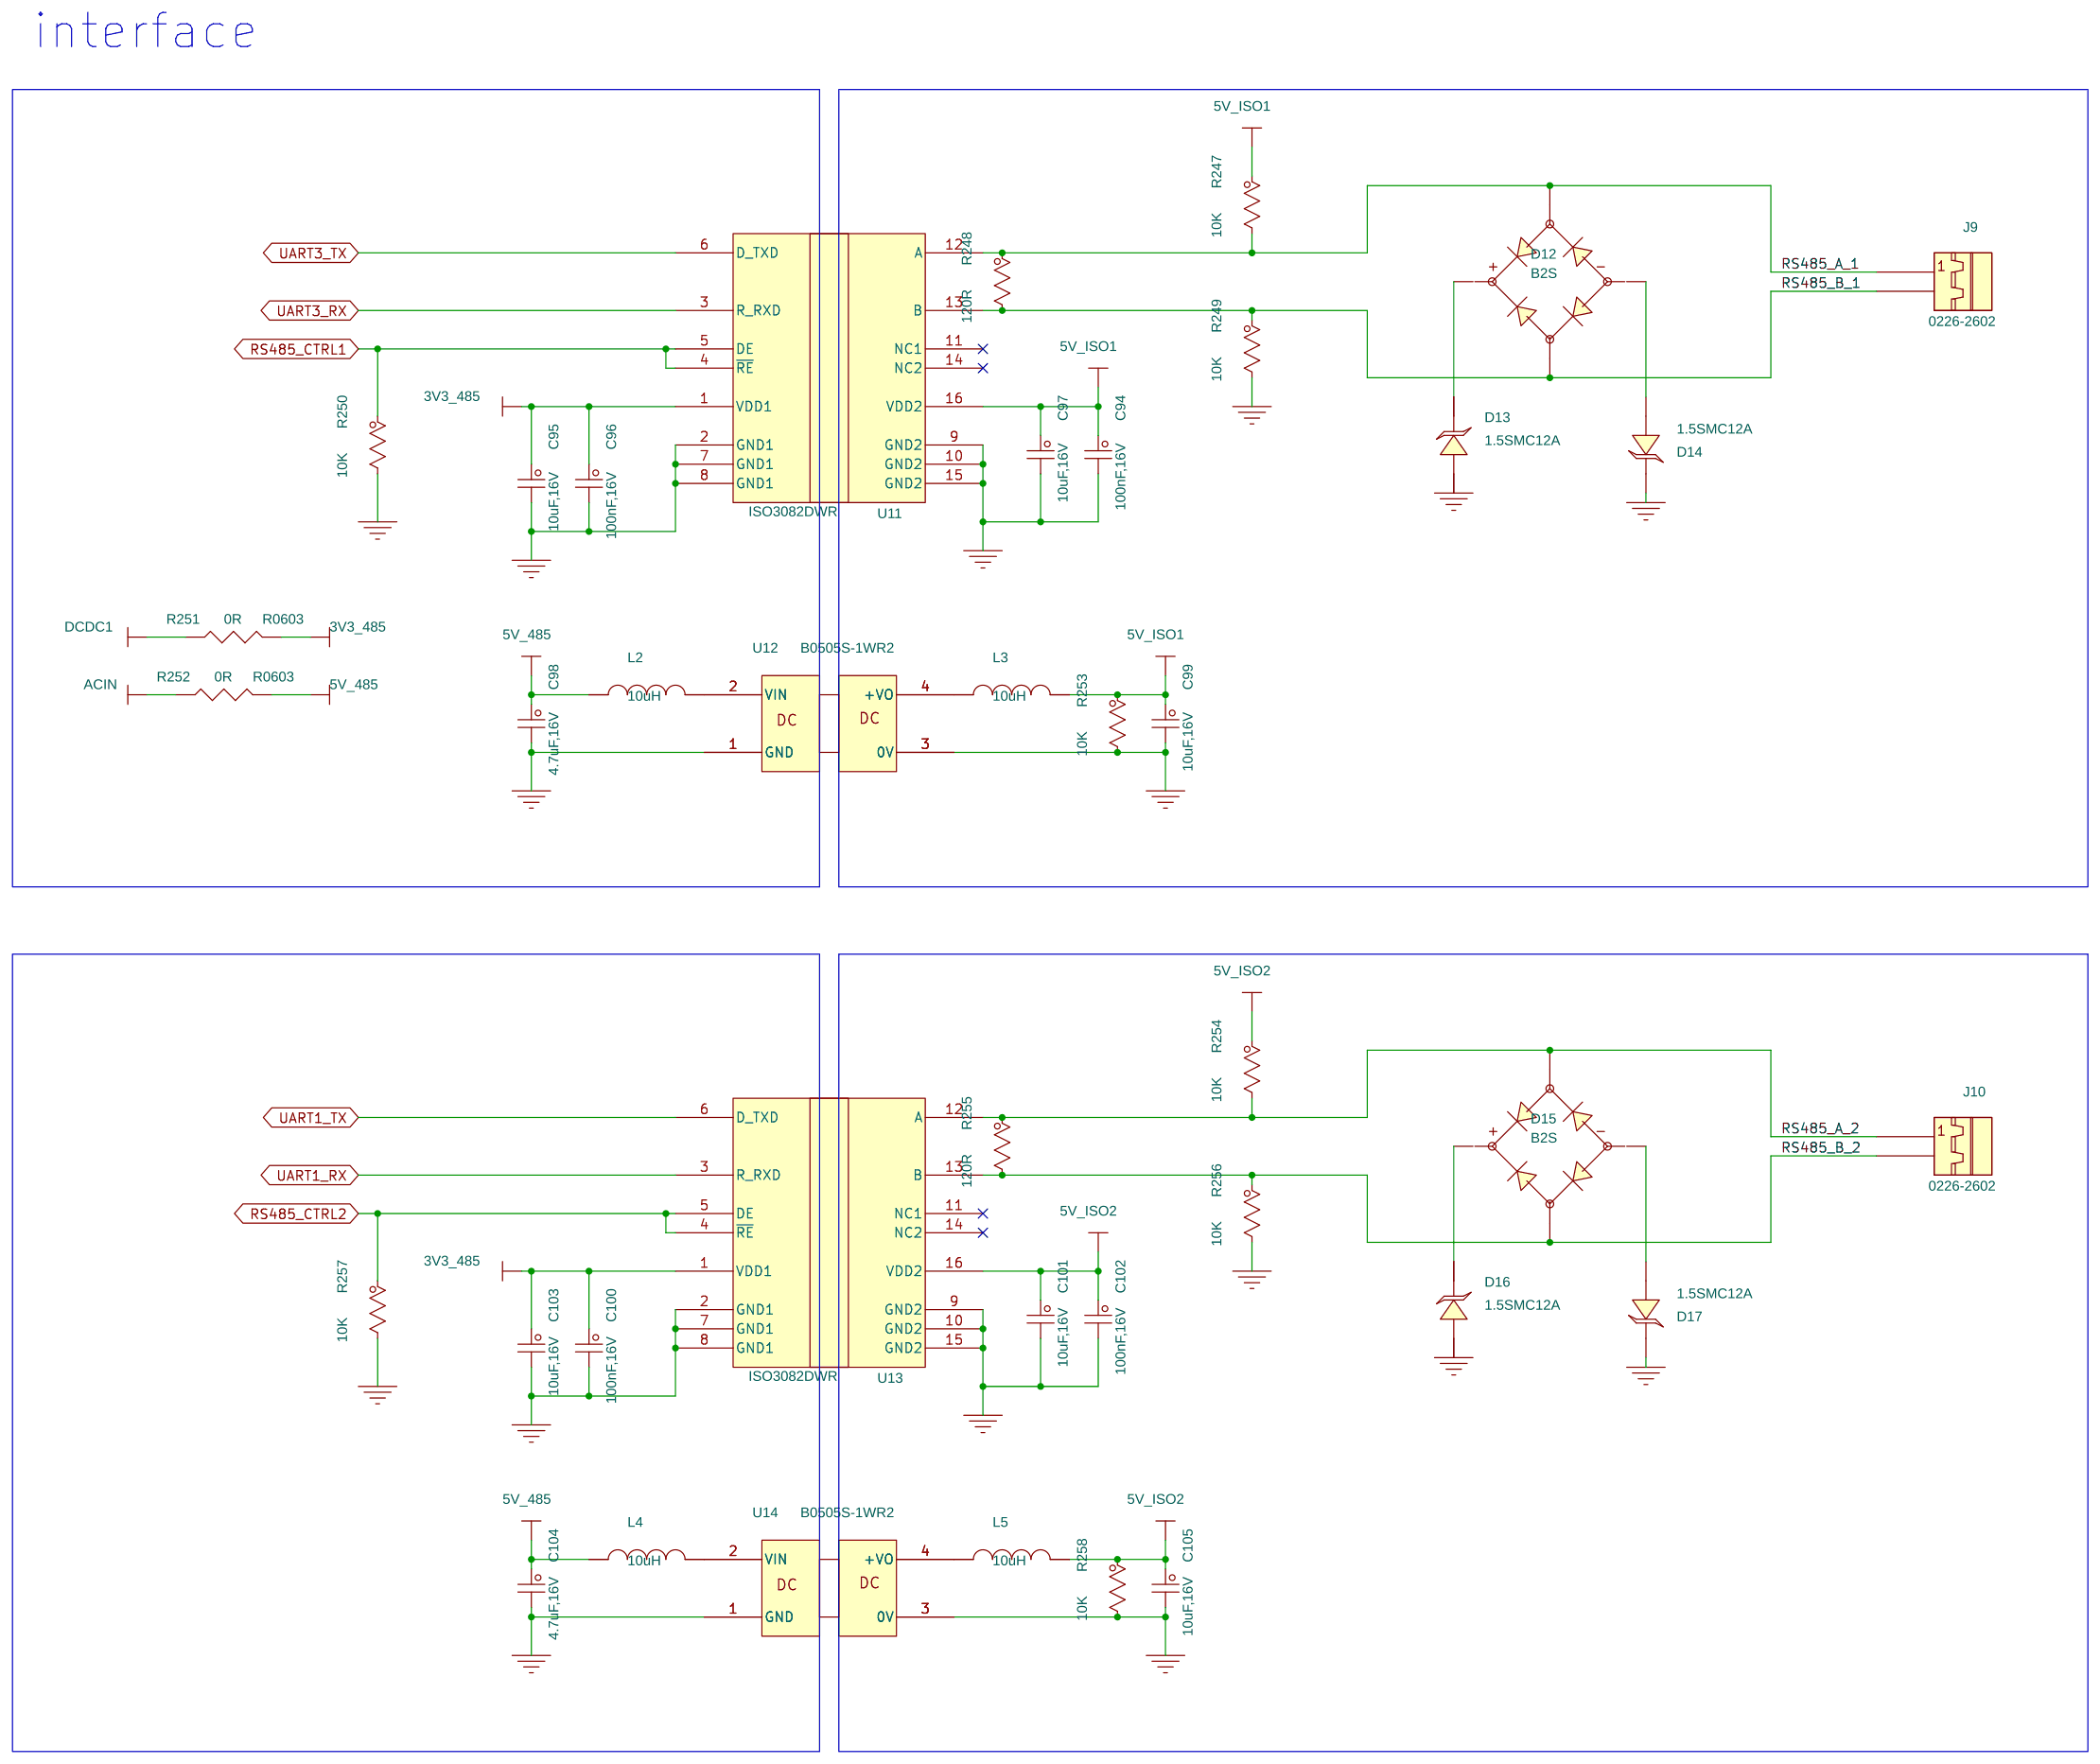
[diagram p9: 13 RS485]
11 14 RMII: size A3; note: RMII
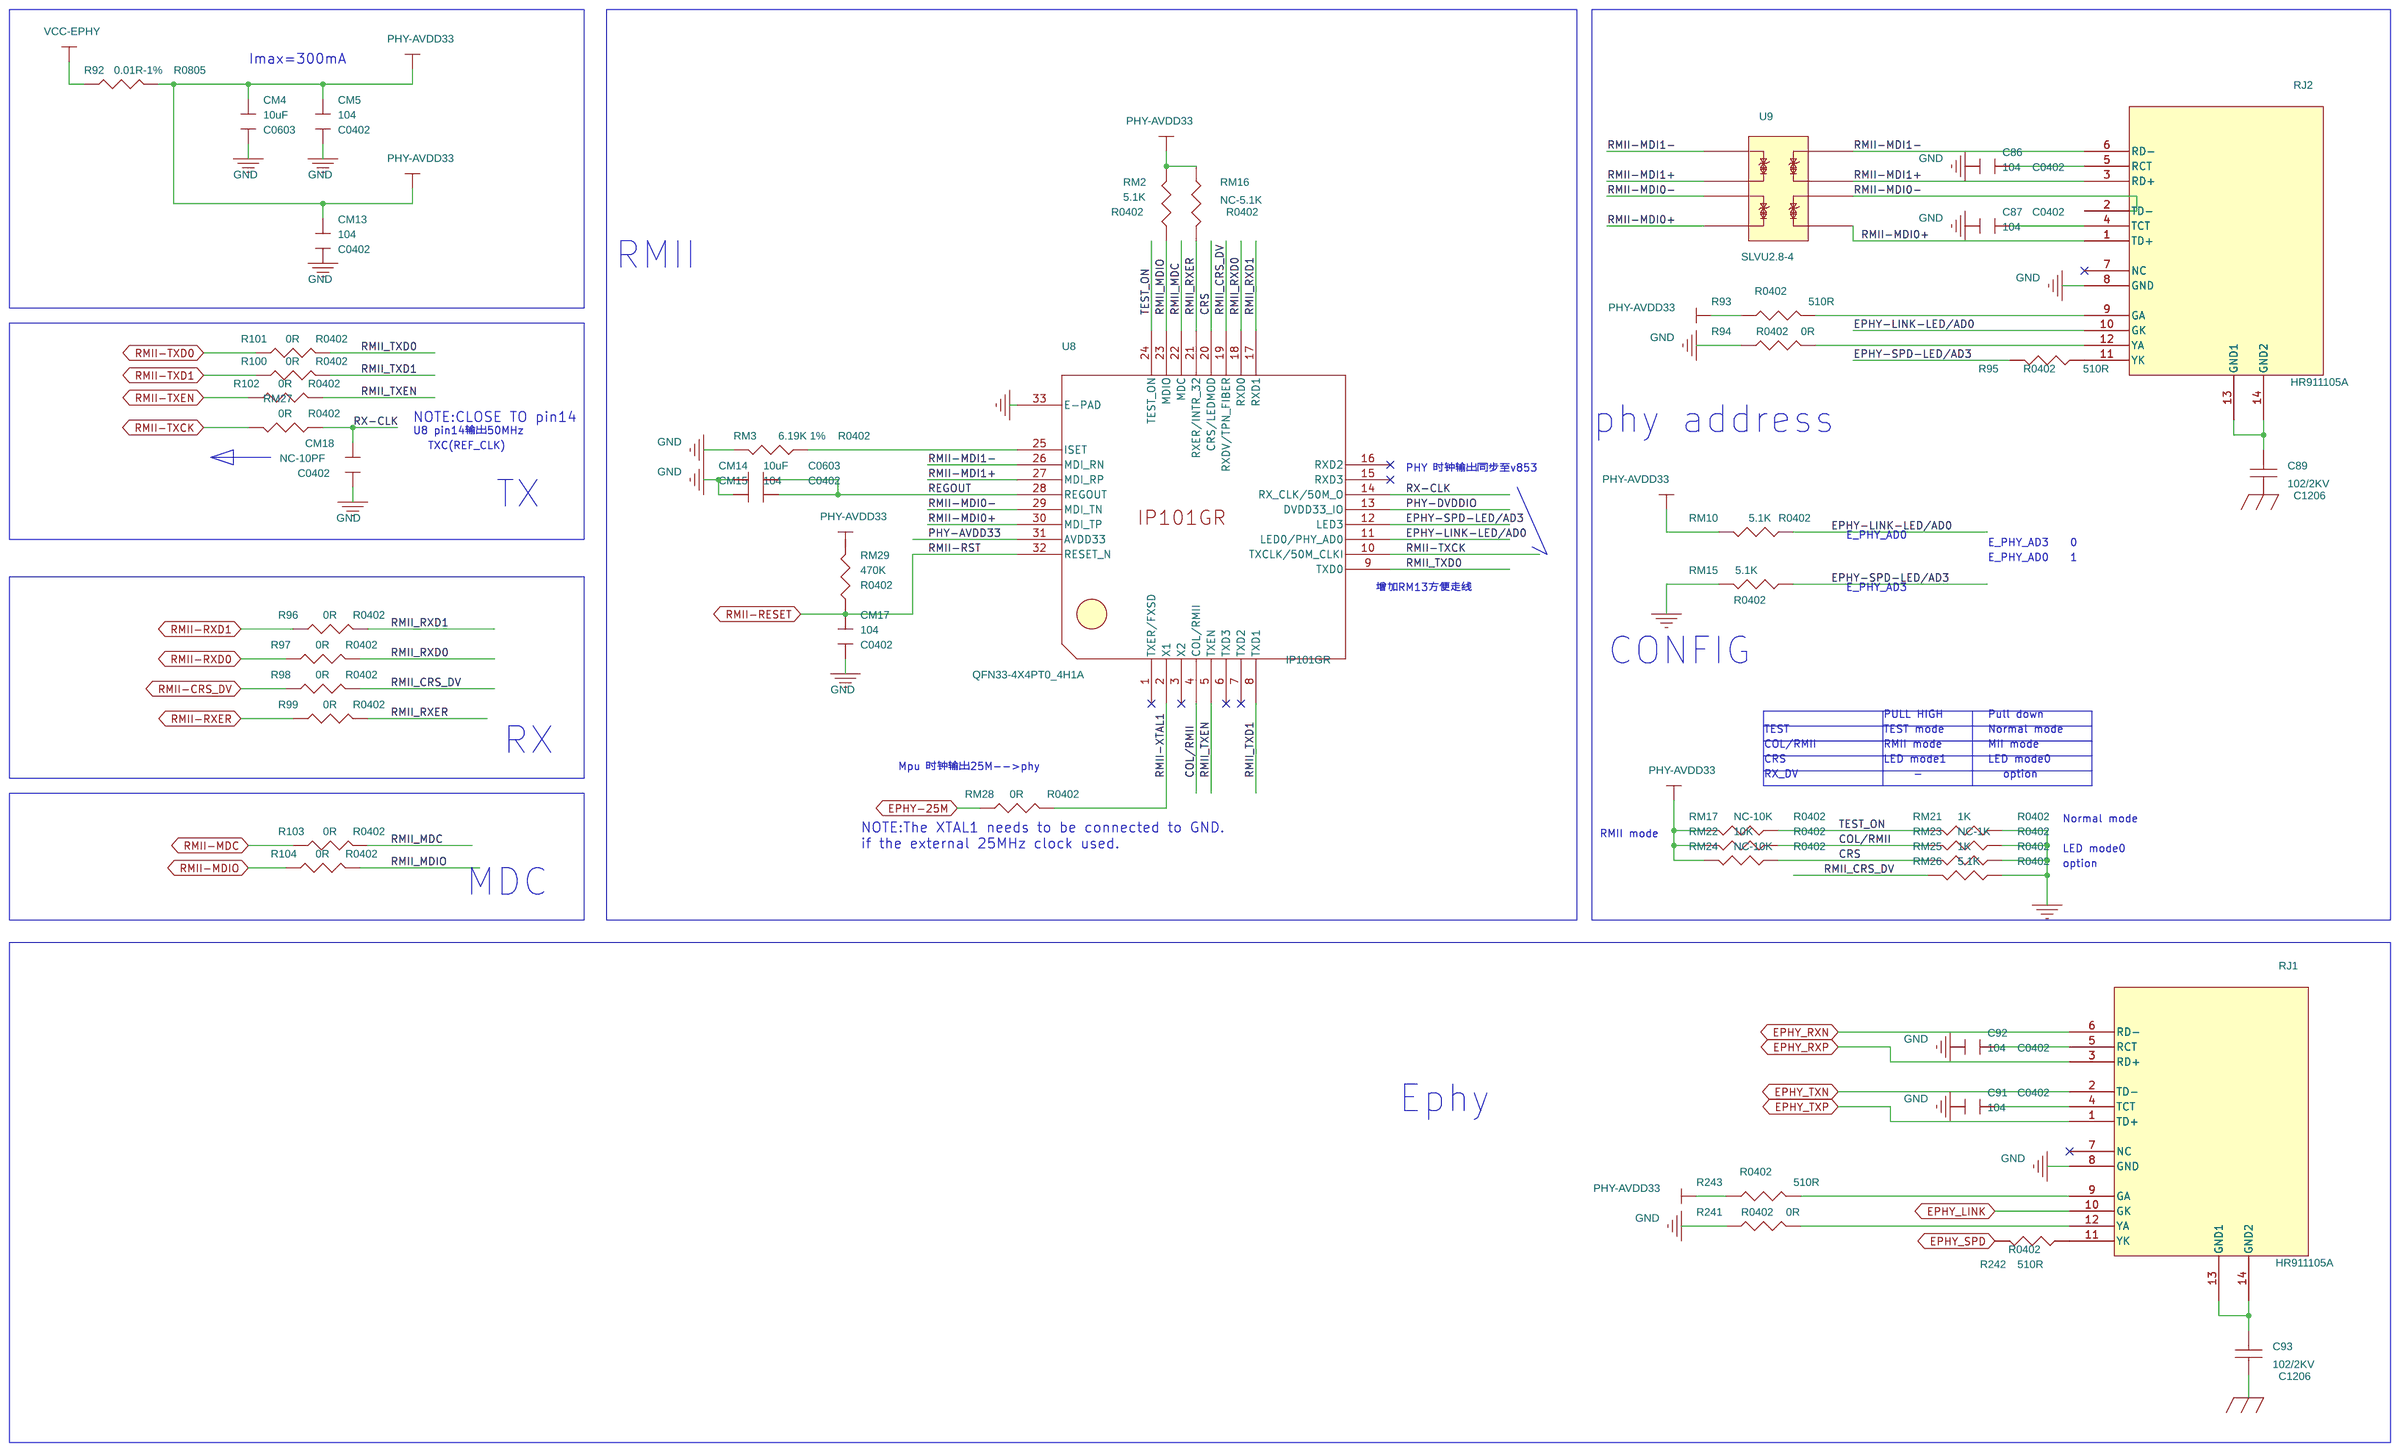
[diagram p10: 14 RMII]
12 15 4G: size A2; note: CAT1
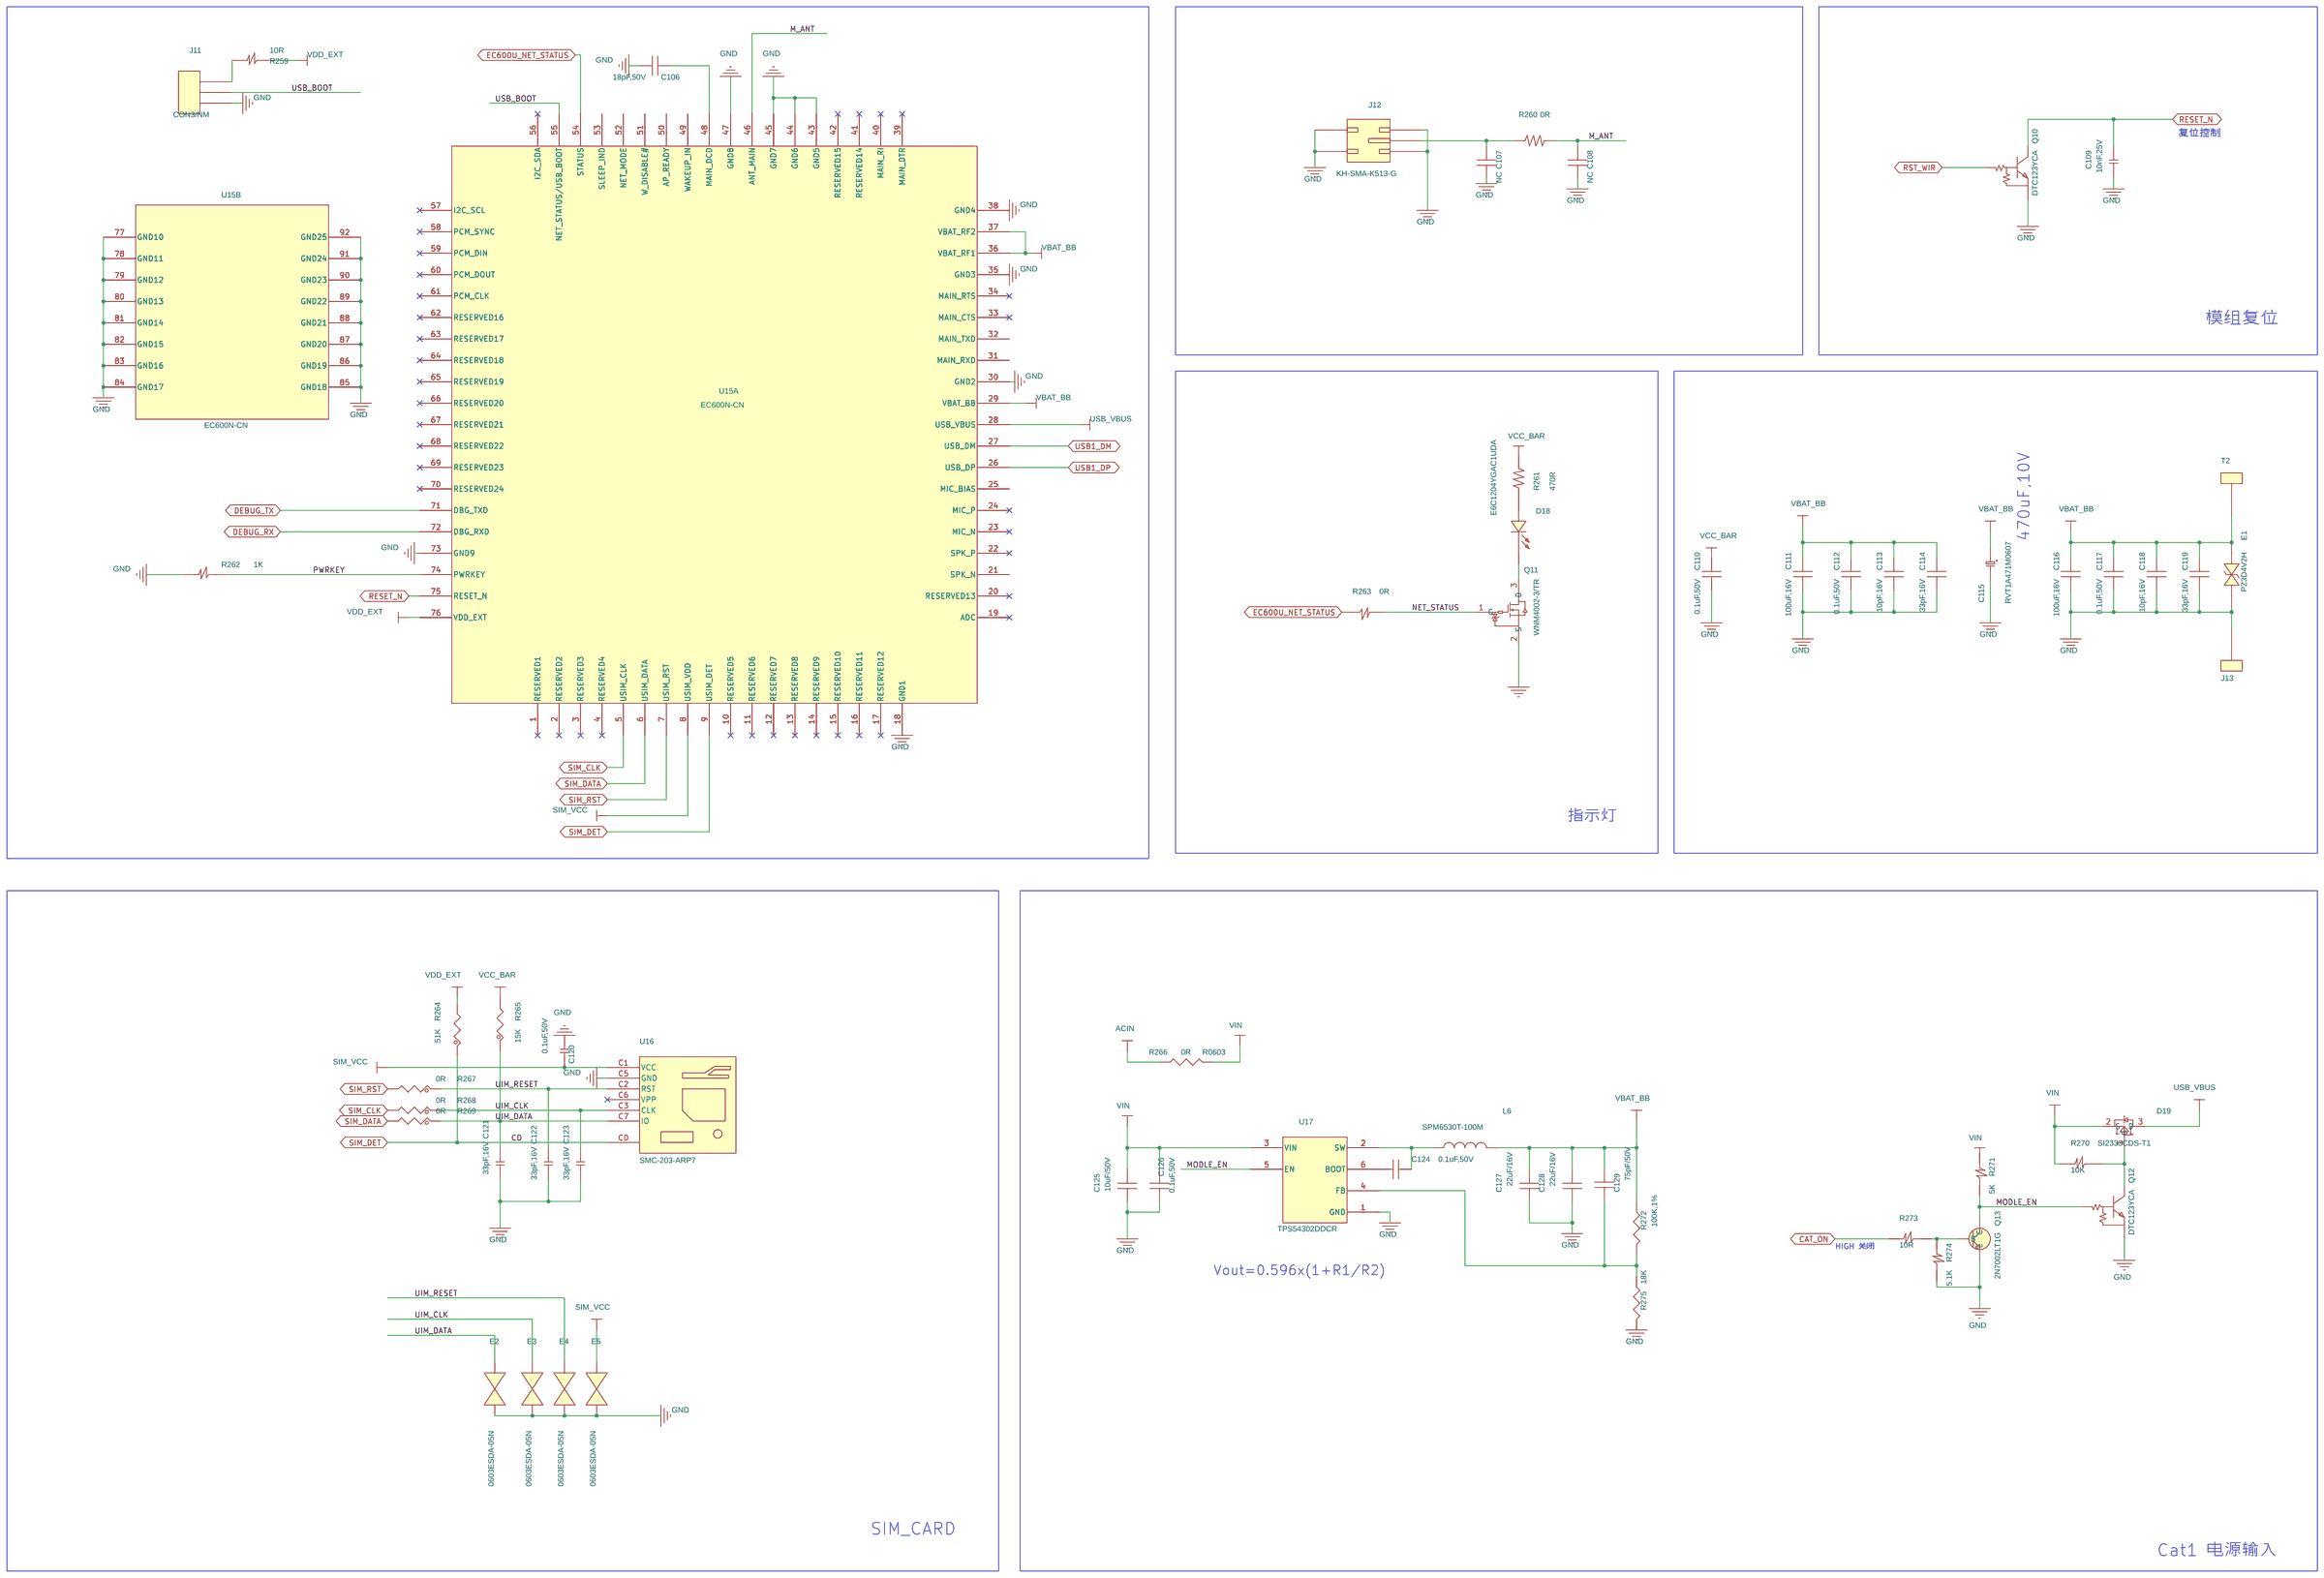
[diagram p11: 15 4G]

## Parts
sheet 05 POWER
BAT1  XH414HG-IV01E  [BAT-XH414HG-C4_8H1_85A]
BATT1  3PIN  [cON3-PT2]
C52  470pF,3KV  [CC200]
C80  104-25V  [C0402]
C83  1uF  [C0402]
C84  NC/10uF-10V  [C0603]
C90  470pF,3KV  [CC200]
CP1  10uF-10V  [C0603]
CP2  4.7uF  [C0603]
CP3  10uF-10V  [C0603]
CP4  22uF  [C0603]
CP5  10uF  [C0603]
CP6  2.2uF  [C0402]
CP7  2.2uF  [C0402]
CP9  2.2uF  [C0402]
CP10  4.7uF  [C0603]
CP11  2.2uF  [C0402]
CP12  2.2uF  [C0402]
CP13  22uF  [C0603]
CP14  2.2uF  [C0402]
CP15  2.2uF  [C0402]
CP16  2.2uF  [C0402]
CP17  10uF  [C0603]
CP18  10uF  [C0603]
CP19  2.2uF  [C0402]
CP20  2.2uF  [C0402]
CP21  4.7uF  [C0402]
CP22  2.2uF  [C0402]
CP23  2.2uF  [C0402]
CP24  100nF  [C0402]
CP25  22uF  [C0603]
CP26  22uF  [C0603]
CP27  4.7uF  [C0402]
CP29  1nF  [C0402]
CP30  1nF  [C0402]
CP31  NC-10uF  [C0603]
CP33  NC-10uF  [C0603]
CP34  NC-10uF  [C0603]
CP35  10uF  [C0603]
CS1  104-25V  [C0402]
CS2  10uF-16V  [C0603]
CS3  47pF  [C0402]
D1  NC/IN5819  [SOD123H14A]
D3  1N5819  [SOD123H14A]
D11  B340A  [SMB_DO_214AA]
DP1  LED-0603-R  [LED0603]
DP3  LED-0603-G  [LED0603]
EC1  NC/5F/2.7V  [SCAP2-PT3_5-8X25H8A]
EC2  NC/5F/2.7V  [SCAP2-PT3_5-8X25H8A]
F2  ASMD1206-200  [F1206]
J3  0226-2602  [con2_0226_2602_5mm]
K9  K2-1109DE-A4SW-01  [K2_1109DE]
K10  K2-1109DE-A4SW-01  [K2_1109DE]
LP1  1uH-2A  [L3X3H1_7A]
LP2  1uH-2A  [L3X3H1_7A]
LP4  1uH-2A  [L3X3H1_7A]
LP5  1uH-2A  [L3X3H1_7A]
LS1  6.8uH-3A-DCR<0.031R  [L2D6X6H2A]
M1  B72220S0140K10  [R300]
Q2  WPM2087  [SOT-23]
Q9  SMBJ22CA  [D_SMB]
R84  43R  [R0805]
R85  NC/0R  [R0603]
R86  43R  [R0805]
R87  1M  [R0402]
R88  10K  [R0402]
R89  1M  [R0402]
RP1  NC-330R  [R0402]
RP2  10K  [R0402]
RP3  NC-0.1R-1%  [R0402]
RP4  NC-2K  [R0402]
RP5  NC-2K  [R0402]
RP6  10K  [R0402]
RP7  0.1R-1%  [R0402]
RP8  1K  [R0402]
RP9  NC-0.1R-1%  [R0402]
RP10  0.1R-1%  [R0402]
RP11  NC-0.1R-1%  [R0402]
RP12  0.1R-1%  [R0402]
RP13  0.1R-1%  [R0402]
RP14  0.1R-1%  [R0402]
RP15  NC-0.1R-1%  [R0402]
RP17  0.1R-1%  [R0402]
RP21  0.1R-1%  [R0402]
RP22  510R  [R0402]
RP23  510R  [R0402]
RP24  0.1R-1%  [R0402]
RP25  10K  [R0402]
RP26  NC-0.1R-1%  [R0402]
RP27  0.01R-1%  [R0805]
RP28  0.01R-1%  [R0805]
RP29  0.1R-1%  [R0402]
RP30  0R  [R0402]
RP31  0.01R-1%  [R0805]
RP33  NC-0R  [R0402]
RP34  0.1R-1%  [R0402]
RP35  0.01R-1%  [R0805]
RP36  0.1R-1%  [R0402]
RP37  NC-0.1R-1%  [R0402]
RP38  NC-0.1R-1%  [R0402]
RP40  NC-0.1R-1%  [R0603]
RP42  NC-0.1R-1%  [R0402]
RP44  NC-0.1R-1%  [R0402]
RP48  0.1R-1%  [R0402]
RP53  0.1R-1%  [R0402]
RP81  0.01R-1%  [R0805]
RP87  20K  [R0402]
RP89  0.1R-1%  [R0402]
RP90  NC-0.1R-1%  [R0402]
RP91  0.1R-1%  [R0402]
RP93  NC-0.1R-1%  [R0402]
RP94  0.1R-1%  [R0402]
RP99  0.1R-1%  [R0402]
RP100  NC-0.1R-1%  [R0402]
RP101  0.1R-1%  [R0402]
RP102  0.1R-1%  [R0402]
RP103  0.1R-1%  [R0402]
RP104  0.1R-1%  [R0402]
RP113  0.1R-1%  [R0402]
RP114  0.1R-1%  [R0402]
RP115  0.1R-1%  [R0402]
RP117  0.01R-1%  [R0805]
RS1  200K  [R0402]
RS2  150K-1%  [R0402]
RS3  100K  [R0402]
RS4  20K-1%  [R0402]
RS5  0.01R-1%  [R0805]
RS6  0.01R-1%  [R0805]
T1  SCM7060-132T  [ind_dlw5bs_2020]
UP1  AXP2101  [QFN40-PT0_4-5X5H0_8A]
US1  SY8105  [SOT23-6]
sheet 06 CPU
C1  1uF  [C0402]
C2  100nF  [C0402]
C3  2.2uF  [C0402]
C5  100nF  [C0402]
C8  1nF  [C0402]
C9  1nF  [C0402]
C12  22pF  [C0402]
C13  18pF  [C0402]
C14  22pF  [C0402]
C15  18pF  [C0402]
C16  100nF  [C0402]
C17  100nF  [C0402]
C18  1nF  [C0402]
C19  1nF  [C0402]
C20  1nF  [C0402]
C28  2.2uF  [C0402]
C31  100nF  [C0402]
C32  2.2uF  [C0402]
C33  470nF  [C0402]
C35  2.2uF  [C0402]
C36  470nF  [C0402]
C37  10uF  [C0603]
C39  100nF  [C0402]
C40  2.2uF  [C0402]
C41  NC-10uF  [C0603]
C42  NC-2.2uF  [C0402]
C43  NC-100nF  [C0402]
ESD15  ESD  [R0402]
HOLE1  B5  [PAD5D3_3]
HOLE2  B5  [PAD5D3_3]
HOLE3  B5  [PAD5D3_3]
HOLE4  B5  [PAD5D3_3]
K1  K2-1109DE-A4SW-01  [K2_1109DE]
R1  NC-10K  [R0402]
R2  0R  [R0402]
R3  NC/0R  [R0402]
R4  NC/0R  [R0402]
R5  10M-5%  [R0402]
R6  0R  [R0402]
R7  NC/200R  [R0402]
R8  0R  [R0402]
R240  0R  [R0402]
TP42  NC  [tp30_smd]
TP43  NC  [tp30_smd]
TP188  NC  [tp30_smd]
TP189  NC  [tp30_smd]
TP190  NC  [tp30_smd]
TP191  NC  [tp30_smd]
TP192  NC  [tp30_smd]
TP197  NC  [tp30_smd]
X1  32.768K-12.5pF  [CRYSTAL-2P-3215-H0_85A]
Y1  24M-16pF-10ppm  [CRYSTAL-4P-3225-H1A]
sheet 07 JTAG/DEBUG
UU1  V853  [bga318-V853-pT0_5-12X12h1_2a]  (sections A,B,C,D,E,F,G,H)
sheet 08 DDR3_16X1
CD1  2.2uF  [C0402]
CD3  2.2uF  [C0402]
CD5  100nF  [C0402]
CD6  NC-10uF  [C0603]
CD7  100nF  [C0402]
CD8  2.2uF  [C0402]
CD9  2.2uF  [C0402]
CD10  100nF  [C0402]
CD11  2.2uF  [C0402]
CD12  100nF  [C0402]
CD13  2.2uF  [C0402]
CD14  100nF  [C0402]
CD15  2.2nF  [C0402]
CD16  100nF  [C0402]
RD1  240R-1%  [R0402]
RD3  240R-1%  [R0402]
RD4  NC-2K-1%  [R0402]
RD5  NC-2K-1%  [R0402]
RD6  NC-100R  [R0402]
RD7  240R-1%  [R0402]
RD8  NC-240R-1%  [R0402]
UD1  DDR3-FBGA96  [fbga96c80p10x13]
sheet 10 MIPI_LCD
C7  100nF  [C0402]
C10  100nF  [C0402]
C21  1uF  [C0402]
C22  4.7uF  [C0402]
C23  104  [C0402]
C26  1uF  [C0402]
C27  105  [C0402]
C29  105  [C0402]
CL1  10uF-10V  [C0603]
CL2  1nF  [C0402]
CL3  4.7uF-25V  [C0805]
CL4  100nF-50V  [C0402]
CL5  NC-1nF  [C0402]
CN2  4pin  [CON4-PT1_25-3_2X6_85H4_8A-UP]
CON1  LCD2  [CON25-PT0_6-3_6X9H1B]
CON3  FPC06-PT0.5  [FPC6-PT05-H2_0B]
D2  1N5819  [SOD-523H0_7A]
DL1  1N5819  [SOD123H14A]
FB1  NC/600R-100M  [L0603]
LL1  4.7uH-DCR<0.1R-1.7A  [L4018]
R14  10K  [R0402]
R19  4.7K  [R0402]
R29  0R  [R0603]
R30  100K  [R0402]
R43  33R  [R0402]
R45  33R  [R0402]
R165  NC/0R  [R0402]
R166  NC/0R  [R0402]
R276  0R  [R0402]
R277  0R  [R0402]
R278  0R  [R0402]
R279  0R  [R0402]
R280  0R  [R0402]
R281  0R  [R0402]
R282  0R  [R0402]
R283  0R  [R0402]
R284  0R  [R0402]
R285  0R  [R0402]
RL1  0R  [R0603]
RL2  0R  [R0402]
RL3  0R  [R0402]
RL4  1M  [R0402]
RL5  10R-1%  [R0402]
RL6  10R-1%  [R0402]
RL7  2K  [R0402]
RL8  2K  [R0402]
RL13  0R  [R0402]
RL14  0R  [R0402]
U2  WL2801E28-5/TR  [SOT23-5]
UL1  STI9287C  [SOT23-6]
sheet 11 MIPI CSI
C4  100nF  [C0402]
C6  100nF  [C0402]
C75  104  [C0402]
C76  104  [C0402]
CON4  OV4689  [CON40_PT1-2X25_6H3A]
R22  2K  [R0402]
R23  2K  [R0402]
R69  100K  [R0402]
R70  100K  [R0402]
R142  2K  [R0402]
R143  2K  [R0402]
R144  100K  [R0402]
R145  100K  [R0402]
R157  33R  [R0402]
R158  33R  [R0402]
sheet 13 RS485
C94  100nF,16V  [C0603]
C95  10uF,16V  [C0805]
C96  100nF,16V  [C0603]
C97  10uF,16V  [C0805]
C98  4.7uF,16V  [C0805]
C99  10uF,16V  [C0805]
C100  100nF,16V  [C0603]
C101  10uF,16V  [C0805]
C102  100nF,16V  [C0603]
C103  10uF,16V  [C0805]
C104  4.7uF,16V  [C0805]
C105  10uF,16V  [C0805]
D12  B2S  [sop4_4x4p7_2p4mm]
D13  1.5SMC12A  [D_SMC]
D14  1.5SMC12A  [D_SMC]
D15  B2S  [sop4_4x4p7_2p4mm]
D16  1.5SMC12A  [D_SMC]
D17  1.5SMC12A  [D_SMC]
J9  0226-2602  [con2_0226_2602_5mm]
J10  0226-2602  [con2_0226_2602_5mm]
L2  10uH  [VLCF5020T]
L3  10uH  [VLCF5020T]
L4  10uH  [VLCF5020T]
L5  10uH  [VLCF5020T]
R247  10K  [R0805]
R248  120R  [R1206]
R249  10K  [R0805]
R250  10K  [R0603]
R251  0R  [R0603]
R252  0R  [R0603]
R253  10K  [R0805]
R254  10K  [R0805]
R255  120R  [R1206]
R256  10K  [R0805]
R257  10K  [R0603]
R258  10K  [R0805]
U11  ISO3082DWR  [SOIC16_10P_5X7P6_1P_27MM]
U12  B0505S-1WR2  [B0505S_1W]
U13  ISO3082DWR  [SOIC16_10P_5X7P6_1P_27MM]
U14  B0505S-1WR2  [B0505S_1W]
sheet 14 RMII
C86  104  [C0402]
C87  104  [C0402]
C89  102/2KV  [C1206]
C91  104  [C0402]
C92  104  [C0402]
C93  102/2KV  [C1206]
CM4  10uF  [C0603]
CM5  104  [C0402]
CM13  104  [C0402]
CM14  10uF  [C0603]
CM15  104  [C0402]
CM17  104  [C0402]
CM18  NC-10PF  [C0402]
R92  0.01R-1%  [R0805]
R93  510R  [R0402]
R94  0R  [R0402]
R95  510R  [R0402]
R96  0R  [R0402]
R97  0R  [R0402]
R98  0R  [R0402]
R99  0R  [R0402]
R100  0R  [R0402]
R101  0R  [R0402]
R102  0R  [R0402]
R103  0R  [R0402]
R104  0R  [R0402]
R241  0R  [R0402]
R242  510R  [R0402]
R243  510R  [R0402]
RJ1  HR911105A  [RJ45_HR911105A]
RJ2  HR911105A  [RJ45_HR911105A]
RM2  5.1K  [R0402]
RM3  6.19K 1%  [R0402]
RM10  5.1K  [R0402]
RM15  5.1K  [R0402]
RM16  NC-5.1K  [R0402]
RM17  NC-10K  [R0402]
RM21  1K  [R0402]
RM22  10K  [R0402]
RM23  NC-1K  [R0402]
RM24  NC-10K  [R0402]
RM25  1K  [R0402]
RM26  5.1K  [R0402]
RM27  0R  [R0402]
RM28  0R  [R0402]
RM29  470K  [R0402]
U8  IP101GR  [QFN33-4X4PT0_4H1A]
U9  SLVU2.8-4  [JEDEC_SO_8]
sheet 15 4G
C106  18pF,50V  [c0603]
C107  NC  [C0402]
C108  NC  [C0402]
C109  10nF,25V  [c0603]
C110  0.1uF,50V  [c0603]
C111  100uF,16V  [C1206]
C112  0.1uF,50V  [c0603]
C113  10pF,16V  [c0603]
C114  33pF,16V  [c0603]
C115  RVT1A471M0607  [SMD_6p3x7p7mm]
C116  100uF,16V  [C1206]
C117  0.1uF,50V  [c0603]
C118  10pF,16V  [c0603]
C119  33pF,16V  [c0603]
C120  0.1uF,50V  [c0603]
C121  33pF,16V  [c0603]
C122  33pF,16V  [c0603]
C123  33pF,16V  [c0603]
C124  0.1uF,50V  [C0603]
C125  10uF/50V  [c1206]
C126  0.1uF,50V  [C0603]
C127  22uF/16V  [C0805]
C128  22uF/16V  [C0805]
C129  75pF/50V  [C0603]
D18  E6C1204YGAC1UDA  [LED0603]
D19  SI2333CDS-T1  [SOT23]
E1  PZ3D4V2H  [SOD-323]
E2  0603ESDA-05N  [l0603]
E3  0603ESDA-05N  [l0603]
E4  0603ESDA-05N  [l0603]
E5  0603ESDA-05N  [l0603]
J11  CON3/NM  [SIP3]
J12  KH-SMA-K513-G  [conh_sma_5p_6p5x6p5_v]
J13  TEST POINT  [TP_S40X40C]
L6  SPM6530T-100M  [smd_7p1x6p5x3p0mm]
Q10  DTC123YCA  [SOT_23]
Q11  WNM4002-3/TR  [sot523]
Q12  DTC123YCA  [SOT_23]
Q13  2N7002LT1G  [SOT23]
R259  10R  [R0603]
R260  0R  [R0402]
R261  470R  [R0603]
R262  1K  [R0603]
R263  0R  [r0603]
R264  51K  [R0603]
R265  15K  [R0603]
R266  0R  [R0603]
R267  0R  [R0603]
R268  0R  [R0603]
R269  0R  [R0603]
R270  10K  [R0603]
R271  5K  [R0603]
R272  100K,1%  [R0603]
R273  10R  [R0603]
R274  5.1K  [R0603]
R275  18K  [R0603]
T2  TEST POINT  [TP_S40X40C]
U15  EC600N-CN  [ec600n-cn]  (sections A,B)
U16  SMC-203-ARP7  [SIM7_16P7X17P7MM]
U17  TPS54302DDCR  [sot23_6]

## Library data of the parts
BAT1 = BAT_6: PAGE: 6
BATT1 = FPC10-PT05A_1
C52 C90 = SMALL_CAP
C80 = CAPACITOR: Page: 7
C1-C3 C5 C8 C9 C12-C20 C28 C31-C33 C35 C36 C39 C40 C42 C43 C75 C76 C83 C84 CD1 CD3 CD5 CD7-CD16 CP6 CP7 CP9 CP11 CP12 CP14-CP17 CP19-CP23 = C-C0402
C37 C41 CD6 CL1 CP1-CP5 CP10 CP13 CP18 CP24 CP29-CP31 CP33-CP35 = C-C0603
CP25 CP26 = CAPACITOR_0: PAGE: 1
CP27 = CAPACITOR_3: PAGE: 1
CS1 = C-C0402-X5R_1
CS2 = C-C0603-X5R_2
CS3 = C-C0402-COG
D1 = DIODE_SCHOTTKY_0
D3 = DIODE: Schottky Barrier，SS32 DO214AC; Created by: JJJ; Manufacturer: 星海; Manufacturer PN: SS32_DO214AC; Part Type: Schottky rectifier; Priority: A; RK PN: SS32
D11 = ZENAR_0: Package: D
DP1 DP3 = LED-0603-G
EC1 EC2 = CAPACITOR_POL: YEMIAN: 8
F2 = FUSE_1A
J3 J9 J10 = 2ERJRC-5.08-2P-4
K1 K9 K10 = K2_1109DE_A4SW_0
LP1 LP2 LP4 LP5 = L-L3225
LS1 = L-L8080
M1 = MOV
Q2 = PMOS_0: Page: 10
Q9 = SMBJ48CA
R1-R8 R22 R23 R69 R70 R84-R89 R142-R145 R157 R158 R240 RD6 RL2 RP1 RP3-RP15 RP17 RP21-RP24 RP26 RP27 RP29 RP30 RP33-RP38 RP40 RP42 RP44 RP48 RP53 RP89-RP91 RP93 RP94 RP99-RP104 RP113-RP115 RP117 = R-R0402-5%
RL1 RP2 RP25 = R-R0603-5%
RP28 RP31 RP81 RS5 RS6 = R-R0805-1%
RP87 = R-R0603-1%
RS1 RS3 = R-R0402-5%_1
RS2 RS4 = R-R0402-1%_0
T1 = TRNSFMR_67115100_0
UP1 = AXP2101_0
US1 = SY8105
ESD15 = 1_1.5KE100A: 1ST PART DESCRIPTION: WILL ESD9B5V Bidirection ESD Protection; Page: 11
HOLE1-HOLE4 TP42 TP43 TP188-TP192 TP197 = T_POINT_R
X1 = CRY-32.768KHz-3215-SMD
Y1 = CRY-24MHz-3225-SMD
UU1 = V853_0621
RD1 RD3-RD5 RD7 RD8 RL5 RL6 = R-R0402-1%
UD1 = DDR3-FBGA96
C4 C6 C7 C10 = C-C0402: PAGE: 2; ROOM: CPU
C21 = CAPACITOR_0: CHIP CAP 50V X7R 0805 ROHS; PAGE: 2; Tolerance: '+80/-20%
C22 = CAPACITOR_0: CHIP CAP  6.3V Y5V 0805 ROHS; PAGE: 2; Tolerance: '+80/-20%
C23 = CAPACITOR_0: CHIP CAP 50V X7R 0402 ROHS; PAGE: 2; Tolerance: +/-10%
C26 = CAPACITOR_0: PAGE: 2; ROOM: DISPLAY&TP
C27 C29 C86 C87 C91 C92 = CAPACITOR_0: PAGE: 2
CL2 CL4 CL5 = C-C0402: PAGE: 2; ROOM: EMMC; mypage: 08
CL3 = C-C0805
CN2 = FPC10-PT05A_2
CON1 = FPC23_0
CON3 = FPC10-PT05A_21
D2 = D_0: Allegro PCB Footprint: d2513A
DL1 = DIO-SS16F_0
FB1 = INDUCTOR_0: RoHS BEAD/600ohm 100Mhz Z=600Ω DCR<0.2Ω 800mA SMT L0603; Package: SMT; Pin Names Rotate: TRUE; Pin Names Visible: FALSE; Pin Numbers Visible: TRUE
LL1 = L-L2520
R14 R30 R93-R95 R241-R243 = RESISTOR: CHIP RESISTOR 1/16W 0402 ROHS; Tolerance: +/-5%
R19 R43 R45 R165 R166 R276-R285 = R: Page: 10
R29 R92 R96-R104 RM2 RM3 RM10 RM15-RM17 RM21-RM29 = R
RL3 RL4 RL13 RL14 = R-R0402-5%: ROOM: EMMC; mypage: 08
RL7 RL8 = R-R0402-5%_0: ROOM: EMMC; mypage: 08
U2 = DS8008_0
UL1 = SY7200A
CON4 = TD030673_7: Page: 10
C94-C105 = Ceramic_Capacitor: Ceramic Capacitor,100nF, 50V,+/-10%, X7R,0603,Fenghua; Manufacturer: Fenghua; Manufacturer P/N: 0603B104K500NT; Myir P/N: 20401.80129; Part Type: Ceramic Capacitor; Reserve Value: 100nF; Datasheet: FENGHUA-Capacitor.pdf
D12 D15 = DIODE_BRIDGE_0
D13 D14 D16 D17 = DIODE_TVS_0
L2-L5 = Inductor
R247-R250 R253-R258 = Resister: Thick Film Resistor,59K,+/-1%,1/16W,-55°C ~ 155°C,SMD,0402,Fenghua; Manufacturer: Fenghua; Manufacturer P/N: RC-02W5902FT; Myir P/N: 20301.00207; Part Type: Thick Film Resistor; Reserve Value: 59K; Datasheet: FH规格书_2018-07-30.pdf
R251 R252 R266 = R1_0805: ROOM: DRAM
U11 U13 = ISO3082DWR
U12 U14 = B0505S-1WR2
C89 C93 = CAP_NP_6
CM4 CM5 CM13-CM15 CM17 CM18 = CAP_2: ROOM: EMAC
RJ1 RJ2 = HR911105A
U8 = IP101GR_0
U9 = SLVU2.8-4
C106-C108 = CAP_NP_1
C109 C120-C123 = Cap
C110-C114 C116-C119 = CAP_NP_0
C115 = 470uF,10V
C124-C129 = CAP_NP
D18 = LED
D19 = SI2333CDS-T1_0
E1 = DIODE_BI_DIR_TRIG: Transient Voltage Suppressing Device.Tiny Packge for ESD/Transient Protection; Created by: JJJ; Manufacturer: Amazing（晶焱科技）; Manufacturer PN: AZ5825-01F; Part Type: ESD_TVS; Priority: A; RK PN: AZ5825-01F
E2-E5 = 0603ESDA-05N
J11 = CON3
J12 = SMA-KHDC3
J13 T2 = TEST_POINT
L6 = INDUCTOR
Q10 Q12 = NPN_D_0
Q11 = WNM4002-3_TR
Q13 = 9013
R259 R262 R263 R270 R271 R273 R274 = RES_v2
R260 R261 = RES1_v2
R264 R265 R267-R269 = RES: RES MF 110 OHM 1/10W 1% AEC-Q200 0402; AGILE_PN: 470-30746; CAD_APPROVED: Yes; FPLIST: RC0402_25,RC0402_HD,0402_CC; HEIGHT: 0.40 MM; MFG_NAME01: KOA SPEER; MFG_PN01: RK73H1ETTP1100F; ROHS: Yes; SIGNAL_MODEL: DEFAULT_RESISTOR_110.000000OHM_2_1; Temp_Range: -55C to +155C; Tolerance: 1%
R272 R275 = RES1
U15 = EC600N-CN
U16 = SMC-203-ARP7
U17 = TPS54302DDCR

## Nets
2.8V: FB1.1 R29.1 U2.5(OUT)
3V3_485: C95.1 C96.1 C100.1 C103.1 R251.2 U11.1(VDD1) U13.1(VDD1)
5V_485: C98.1 C104.1 L2.1 L4.1 R252.2
5V_ISO1: C94.1 C97.1 C99.1 L3.2 R247.1 R253.1 U11.16(VDD2)
5V_ISO2: C101.1 C102.1 C105.1 L5.2 R254.1 R258.1 U13.16(VDD2)
12V: C52.1 CS2.1 Q9.2 RS1.1 T1.1(IN1) US1.4(IN)
AGND: C32.2 C33.1 C36.1 R8.2 UU1.L21(AGND)
AVCC: C32.1 RP26.2 UU1.J19(AVCC)
AVDD-CSI: CON4.12(AVDD) RP48.2
DVDD-CSI: CON4.10(DVDD) RP53.2 RP99.2
GND: BAT1.2 BATT1.3 C1.1 C2.1 C3.1 C4.2 C5.1 C6.2 C7.2 C8.1 C9.1 C10.2 C12.1 C13.1 C14.1 C15.1 C16.1 C17.1 C18.1 C19.1 C20.1 C21.1 C22.1 C23.1 C26.1 C27.1 C28.2 C29.1 C31.2 C35.1 C37.2 C39.2 C40.2 C41.2 C42.2 C43.2 C75.2 C76.1 C80.1 C83.1 C84.1 C86.2 C87.1 C90.2 C91.1 C92.2 C95.2 C96.2 C98.2 C100.2 C103.2 C104.2 C106.1 C107.1 C108.1 C109.1 C110.2 C111.2 C112.2 C113.2 C114.2 C115.2 C116.2 C117.2 C118.2 C119.2 C120.2 C121.1 C122.1 C123.1 C125.1 C126.1 C127.1 C128.1 CD1.2 CD3.2 CD5.2 CD6.2 CD7.2 CD8.2 CD9.2 CD10.2 CD11.2 CD12.2 CD13.2 CD14.2 CD15.2 CD16.2 CL1.2 CL2.2 CL3.2 CL4.2 CL5.2 CM4.1 CM5.1 CM13.1 CM14.2 CM15.2 CM17.1 CM18.1 CN2.4 CON1.4(GND1) CON1.9(GND2) CON1.12(GND3) CON1.15(GND4) CON1.18(GND5) CON1.21(GND6) CON1.24(GND7) CON1.25(GND8) CON1.26 CON1.27 CON3.1 CON3.7 CON3.8 CON4.1(DGND) CON4.4(DGND1) CON4.6(DGND2) CON4.9(DGND3) CON4.14(DGND5) CON4.17(DGND6) CON4.20(DGNG7) CON4.23(DGND8) CON4.26(DGND9) CON4.29(DGND10) CON4.32(DGND11) CON4.35(DGND12) CON4.37(GND13) CON4.40(GND14) CON4.41(GND) CON4.42(GND1) CP1.1 CP2.2 CP3.1 CP4.1 CP5.1 CP6.2 CP7.1 CP9.1 CP10.2 CP11.1 CP12.1 CP13.1 CP14.1 CP15.1 CP16.1 CP17.1 CP18.1 CP19.1 CP20.2 CP21.1 CP22.2 CP23.2 CP24.1 CP25.1 CP26.1 CP27.2 CP29.1 CP30.1 CP31.1 CP33.1 CP34.1 CP35.1 CS2.2 DP3.2 E1.1 E2.2 E3.2 E4.2 E5.2 EC2.2 ESD15.2(CATHODE) HOLE1.1(TP) HOLE2.1(TP) HOLE3.1(TP) HOLE4.1(TP) J11.3 J12.2 J12.3 J12.4 J12.5 J13.1 K1.2 K9.2 K10.2 Q9.1 Q10.2(S) Q11.2(S) Q12.2(S) Q13.2(E) R2.1 R3.1 R4.1 R8.1 R30.2 R88.1 R89.1 R94.2 R241.2 R250.2 R257.2 R262.1 R274.2 R275.1 RD1.2 RD3.2 RD5.2 RD7.2 RD8.2 RJ1.8(GND) RJ2.8(GND) RL4.2 RL5.2 RL6.2 RM3.1 RM15.2 RM21.2 RM23.2 RM25.2 RM26.2 RP1.1 RP2.2 RS3.2 RS4.2 T1.4(OUT1) U2.2(GND) U8.33(E-PAD) U11.2(GND1) U11.7(GND1) U11.8(GND1) U12.1(GND) U13.2(GND1) U13.7(GND1) U13.8(GND1) U14.1(GND) U15.18(GND1) U15.30(GND2) U15.35(GND3) U15.38(GND4) U15.43(GND5) U15.44(GND6) U15.45(GND7) U15.47(GND8) U15.73(GND9) U15.77(GND10) U15.78(GND11) U15.79(GND12) U15.80(GND13) U15.81(GND14) U15.82(GND15) U15.83(GND16) U15.84(GND17) U15.85(GND18) U15.86(GND19) U15.87(GND20) U15.88(GND21) U15.89(GND22) U15.90(GND23) U15.91(GND24) U15.92(GND25) U16.C5(GND) U17.1(GND) UD1.A9(VSS#9) UD1.B1(VSSQ#1) UD1.B3(VSS#6) UD1.B9(VSSQ#7) UD1.D1(VSSQ#2) UD1.D8(VSSQ#5) UD1.E1(VSS#1) UD1.E2(VSSQ#4) UD1.E8(VSSQ#6) UD1.F9(VSSQ#8) UD1.G1(VSSQ#3) UD1.G8(VSS#7) UD1.G9(VSSQ#9) UD1.J2(VSS#5) UD1.J8(VSS#8) UD1.M1(VSS#2) UD1.M9(VSS#10) UD1.P1(VSS#3) UD1.P9(VSS#11) UD1.T1(VSS#4) UD1.T9(VSS#12) UL1.2(GND) UP1.3(GND1) UP1.41(EPAD) US1.3(GND) UU1.A1(GND0) UU1.A14(GND1) UU1.A23(GND2) UU1.AA5(GND73) UU1.AB4(GND74) UU1.AB10(GND75) UU1.AB14(GND76) UU1.AB20(GND77) UU1.AC1(GND78) UU1.AC23(GND79) UU1.B4(GND3) UU1.B20(GND4) UU1.C11(GND5) UU1.D7(GND6) UU1.D15(GND7) UU1.D22(GND8) UU1.F11(GND9) UU1.F13(GND10) UU1.F17(GND11) UU1.G2(GND12) UU1.G20(GND13) UU1.H8(GND14) UU1.H9(GND15) UU1.H10(GND16) UU1.H11(GND17) UU1.H12(GND18) UU1.H16(GND19) UU1.J8(GND20) UU1.J10(GND21) UU1.J11(GND22) UU1.J13(GND23) UU1.J14(GND24) UU1.J16(GND25) UU1.J18(GND26) UU1.K1(GND27) UU1.K9(GND28) UU1.K11(GND29) UU1.K13(GND30) UU1.K15(GND31) UU1.K16(GND32) UU1.K22(GND33) UU1.L8(GND34) UU1.L9(GND35) UU1.L10(GND36) UU1.L11(GND37) UU1.L13(GND38) UU1.L14(GND39) UU1.L15(GND40) UU1.L20(GND41) UU1.M8(GND42) UU1.M11(GND43) UU1.M13(GND44) UU1.M15(GND45) UU1.M16(GND46) UU1.N9(GND47) UU1.N10(GND48) UU1.N11(GND49) UU1.N13(GND50) UU1.N15(GND51) UU1.N16(GND52) UU1.N18(GND53) UU1.P11(GND54) UU1.P13(GND55) UU1.P15(GND56) UU1.R11(GND57) UU1.R13(GND58) UU1.R15(GND59) UU1.R18(GND60) UU1.R20(GND61) UU1.T10(GND62) UU1.T11(GND63) UU1.T16(GND64) UU1.U20(GND65) UU1.V9(GND66) UU1.V13(GND67) UU1.V17(GND68) UU1.Y7(GND69) UU1.Y11(GND70) UU1.Y15(GND71) UU1.Y22(GND72) Y1.2(GND1) Y1.4(GND2) ; also on sheet 13 14 15
GND_EARTH: C89.2 C93.2
GND_EARTH1: C52.2 C90.1
GND_ISO: C99.2 R253.2 U12.3(0V)
GND_ISO1: C94.2 C97.2 D13.1(ANODE) D14.2(CATHODE) R249.2 U11.9(GND2) U11.10(GND2) U11.15(GND2)
GND_ISO2: C101.2 C102.2 C105.2 D16.1(ANODE) D17.2(CATHODE) R256.2 R258.2 U13.9(GND2) U13.10(GND2) U13.15(GND2) U14.3(0V)
VBAT: BATT1.1 CP7.2 CP27.1 R85.2 UP1.33(BAT)
VBAT2: BAT1.1 UP1.27(VBACKUP)
VBAT_BB: C110.1 C111.1 C112.1 C113.1 C114.1 C115.1 C116.1 C117.1 C118.1 C119.1 C127.2 C128.2 C129.1 E1.2 L6.2 R272.2 T2.1 U15.29(VBAT_BB) U15.36(VBAT_RF1) U15.37(VBAT_RF2)
VCC18-MCSI: C6.1 RP29.2 UU1.H15(VCC18_MCSI)
VCC18-MDSI: C10.1 RP34.2 UU1.H14(VCC18-MDSI)
VCC18-PF: RP36.2 ; also on sheet 14
VCC33-PF: RP114.2 ; also on sheet 14
VCC33-USB: C16.2 RP90.2 RP94.2 UU1.C13(VCC33_USB)
VCC-3V3: C27.2 FB1.2 RP12.2 U2.1(IN) ; also on sheet 14
VCC-CARD: RP7.2 ; also on sheet 13
VCC-CTP: C26.2 CON3.6 RP17.2
VCC-DRAM: CD1.1 CD3.1 CD6.1 CD7.1 CD8.1 CD9.1 CD10.1 CD11.1 CD12.1 CD13.1 CD14.1 CD15.1 RD4.1 RP35.2 UD1.A1(VDDQ#1) UD1.A8(VDDQ#6) UD1.B2(VDD#3) UD1.C1(VDDQ#2) UD1.C9(VDDQ#9) UD1.D2(VDDQ#4) UD1.D9(VDD#7) UD1.E9(VDDQ#8) UD1.F1(VDDQ#3) UD1.G7(VDD#5) UD1.H2(VDDQ#5) UD1.H9(VDDQ#7) UD1.K2(VDD#4) UD1.K8(VDD#6) UD1.N1(VDD#1) UD1.N9(VDD#8) UD1.R1(VDD#2) UD1.R9(VDD#9) UU1.T12(VCC_DRAM0) UU1.T13(VCC_DRAM1) UU1.T14(VCC_DRAM2) UU1.T15(VCC_DRAM3)
VCC-EMMC: RP14.2 ; also on sheet 15
VCC-EPHY: R92.1 RP115.2 ; also on sheet 14
VCC-IO: C28.1 C31.1 R19.1 RL7.1 RL8.1 RP91.2 UU1.L18(VCC_IO) ; also on sheet 13
VCC-LDOA: C3.2 RP40.1 UU1.J6(VCC_LDOA)
VCC-MIPI-IO: C23.2 CON1.3(IOVCC1.8V) R14.1 RP113.2
VCC-MIPI-LCD: C22.2 C29.2 CON1.2(VCC2.8V) R29.2 R166.2
VCC-PA: C4.1 R22.2 R23.2 R69.2 R70.2 R142.2 R143.2 R144.2 R145.2 RP44.2 RP89.2 UU1.E13(VCC_PA)
VCC-PC: RP13.2 RP42.2 ; also on sheet 15
VCC-PD: C7.1 RP24.2 UU1.F9(VCC_PD)
VCC-PE: RP9.2 RP10.2 RP100.2 ; also on sheet 14
VCC-PG: RP21.2 RP37.2 ; also on sheet 14
VCC-PI: RP4.1 RP5.1 RP11.2 RP104.2 ; also on sheet 14
VCC-PLL: C1.2 C2.2 R7.1 RP93.2 RP102.2 UU1.G6(VCC_PLL)
VCC-RTC: CP23.1 R1.2 R240.1 RP6.1 UP1.28(RTCLDO)
VDD09-USB: C17.2 RP31.2 RP38.2 UU1.D13(VDD09_USB)
VDD18-DRAM: CD5.1 RP3.2 RP103.2 UU1.R16(VDD18_DRAM)
VDD-SYS: C37.1 C39.1 C40.1 C41.1 C42.1 C43.1 RP28.2 UU1.P8(VDD_SYS0) UU1.P9(VDD_SYS1) UU1.R8(VDD_SYS2) UU1.R9(VDD_SYS3) UU1.T8(VDD_SYS4) UU1.T9(VDD_SYS5)
VDD-SYSFB: UP1.4(FB3) UU1.N8(VDD_SYSFB)
VDD_EXT: R259.2 R264.2 U15.76(VDD_EXT)
VIN: C125.2 C126.2 D19.2(S) R261.1 R266.2 R270.1 R271.1 U17.3(VIN)
ACIN: CP1.2 D1.1 D3.1(A) Q2.1(GATE) R88.2 R252.1 R266.1 RS5.2 RS6.2 UP1.37(VBUS) ; also on sheet 13
ALDO1: CP12.2 RP3.1 RP93.1 RP104.1 UP1.18(ALDO1)
ALDO2: CP14.2 RP9.1 RP15.1 UP1.19(ALDO2)
ALDO3: CP15.2 RP11.1 RP90.1 UP1.16(ALDO3)
ALDO4: CP16.2 UP1.15(ALDO4)
AP-NMI: C9.2 RP6.2 UP1.38(IRQ) UU1.L4(NMI)
AP-RESET: C8.2 CP29.2 R1.1 RP22.2 UP1.29(PWROK) UU1.G3(RESET)
BLDO1: RP26.1 RP29.1 RP34.1 RP36.1 RP37.1 RP40.2 RP42.1 RP89.1 RP100.1 RP101.1 RP102.1 RP103.1 RP113.1 RP117.1
BLDO2: CP21.2 RP48.1 UP1.14(BLDO2)
BLDOIN: CP17.2 RP30.2 RP33.2 UP1.13(BLDOIN)
CAT_ON: R273.1 ; also on sheet 14
CHGLED: DP1.2 UP1.1(CHGLED)
COL/RMII: RM22.2 RM23.1 U8.4(COL/RMII)
CPUS-LDO: CP20.1 RP38.1 UP1.10(CPUSLDO)
CRS: RM24.2 RM25.1 U8.20(CRS/LEDMOD)
CSI-A-CKN: CON4.22(CKN-A) UU1.B14(PA1/MIPIA_RX_CK0N/NCSI_D9)
CSI-A-CKP: CON4.21(CKP-A) UU1.B15(PA0/MIPIA_RX_CK0P/NCSI_D8)
CSI-A-D0N: CON4.16(D0N-A) UU1.A17(PA5/MIPIA_RX_D0N/NCSI_D13)
CSI-A-D0P: CON4.15(D0P-A) UU1.B17(PA4/MIPIA_RX_D0P/NCSI_D12)
CSI-A-D1N: CON4.19(D1N-A) UU1.B16(PA2/MIPIA_RX_D1N/NCSI_D10)
CSI-A-D1P: CON4.18(D1P-A) UU1.A16(PA3/MIPIA_RX_D1P/NCSI_D11)
CSI-B-CKN: CON4.31(CKN-B) UU1.A22(PA10/MIPIB_RX_CK0N/NCSI_HSYNC)
CSI-B-CKP: CON4.30(CKP-B) UU1.B21(PA11/MIPIB_RX_CK0P/NCSI_VSYNC)
CSI-B-D0N: CON4.25(D2N__D0N-B) UU1.B18(PA6/MIPIB_RX_D0N/NCSI_D14)
CSI-B-D0P: CON4.24(D2P__D0P-B) UU1.B19(PA7/MIPIB_RX_D0P/NCSI_D15)
CSI-B-D1N: CON4.28(D3N__D1N-B) UU1.A19(PA8/MIPIB_RX_D1N)
CSI-B-D1P: CON4.27(D3P__D1P-B) UU1.A20(PA9/MIPIB_RX_D1P)
CTP-INT: CON3.2 ; also on sheet 14
CTP-RST: CON3.3 R19.2
CTP-SCK: CON3.5 RL8.2
CTP-SDA: CON3.4 RL7.2
DC1SW: CP6.1 RP17.1 RP24.1 UP1.20(DLDO1/DC1SW)
DCDC1: R251.1 RP1.2 RP7.1 RP10.1 RP12.1 RP13.1 RP14.1 RP21.1 RP25.2 RP30.1 RP44.1 RP81.2 RP91.1 RP94.1 RP114.1 RP115.1
DCDC3: RP27.1 RP28.1 RP31.1
DCDC4: CP18.2 CP34.2 LP5.2 RP35.1 UP1.9(FB4)
DCDC5: CP5.2 CP35.2 LP1.1 RP99.1 UP1.32(GPIO1)
DCXO-XIN: C13.2 UU1.H1(DXIN) Y1.1(XIN)
DCXO-XOUT: R6.1 UU1.G1(DXOUT)
DEBUG_RX: U15.72(DBG_RXD)
DEBUG_TX: U15.71(DBG_TXD)
DLDO2: CP22.1 RP53.1 UP1.11(DLDO2/DC4SW)
EC600U_NET_STATUS: R263.2 U15.54(STATUS)
EPHY-25M: RM28.2 ; also on sheet 14
EPHY-LINK-LED/AD0: RJ2.10(GK) RM10.2 U8.11(LED0/PHY_AD0)
EPHY-SPD-LED/AD3: R95.2 RM15.1 U8.12(LED3)
EPHY_LINK: RJ1.10(GK) ; also on sheet 14
EPHY_RXN: RJ1.6(RD-) ; also on sheet 14
EPHY_RXP: RJ1.3(RD+) ; also on sheet 14
EPHY_SPD: R242.2 ; also on sheet 14
EPHY_TXN: RJ1.2(TD-) ; also on sheet 14
EPHY_TXP: RJ1.1(TD+) ; also on sheet 14
FEL: ESD15.1(ANODE) K1.1 UU1.P16(FEL)
GPADC1: C18.2 R165.2 UU1.R19(GPADC1)
GPADC2: C20.2 TP42.1(TP) UU1.N19(GPADC2)
GPADC3: C19.2 TP43.1(TP) UU1.L19(GPADC3)
IOVDD-CSI: CON4.13(DOVDD) RP15.2 RP101.2
IR-CUT-CTRL+: R45.2 UU1.D11(PD14/LCD_D20/I2S1_DOUT1/I2S1_DIN1/DMIC_DATA1)
IR-CUT-CTRL-: R43.2 UU1.E9(PD13/LCD_D19/I2S1_DOUT0DMIC_DATA2)
JTAG-SEL: R3.2 UU1.L16(JTAG_SEL)
LCD-PWM: RL2.1 UU1.E11(PD22/PWM9)
LCD-VCC-EN: R30.1 RL14.2 U2.3(EN)
LX3-OUT: CP13.2 CP33.2 LP4.2 RP27.2
M_ANT: C108.2 R260.1 U15.46(ANT_MAIN)
MBIAS: C35.2 UU1.H23(MBIAS)
MCLK-A: CON4.5(MCLK0) R157.1
MCLK-B: CON4.36(MCLK1) R158.1
MIPI-CSI-MCLK-A: R157.2 UU1.C17(PA12/NCSI_D0/MIPI_CSI_MCLK0/UART0_TX)
MIPI-CSI-MCLK-B: R158.2 UU1.C15(PA13/NCSI_D1/MIPI_CSI_MCLK1/UART0_RX)
MIPI-CSI-PWDN-A: CON4.3(PWRDN0) R70.1 UU1.D19(PA19/NCSI_D7/WIEGAND_D1/UART3_CTS)
MIPI-CSI-PWDN-B: CON4.38(PWRDN1) R145.1 UU1.E20(PA21/NCSI_PCLK)
MIPI-CSI-RSTN-A: C75.1 CON4.2(RESET0) R69.1 UU1.C19(PA18/NCSI_D6/WIEGAND_D0/UART3_RTS)
MIPI-CSI-RSTN-B: C76.2 CON4.39(RESRT1) R144.1 UU1.E19(PA20/NCSI_MCLK/CSI_SM_VS/TCON_TRIG)
MIPI-DSI-CKN: R278.2 UU1.B5(PD5/LCD_D7/PWM4/RMII_TXD1/DSI_CKN)
MIPI-DSI-CKP: R277.2 UU1.B6(PD6/LCD_D10/PWM5/RMII_TXD0/DSI_CKP)
MIPI-DSI-D0N: R282.2 UU1.A8(PD1/LCD_D3/PWM0/RMII_RXD1/DSI_D0N)
MIPI-DSI-D0P: R281.2 UU1.B8(PD2/LCD_D4/PWM1/RMII_RXD0/DSI_D0P)
MIPI-DSI-D1N: R280.2 UU1.B7(PD3/LCD_D5/PWM2/RMII_CRS_DV/DSI_D1N)
MIPI-DSI-D1P: R279.2 UU1.A7(PD4/LCD_D6/PWM3/RMII_RXER/DSI_D1P)
MIPI-DSI-D2N: R276.2 UU1.A4(PD7/LCD_D11/PWM6/RMII_TXCK/DSI_D2N)
MIPI-DSI-D2P: R283.2 UU1.A5(PD9/LCD_D13/PWM8/DSI_D2P)
MIPI-DSI-D3N: R284.2 UU1.B2(PD10/LCD_D14/I2S1_MCLK/DSI_D3N)
MIPI-DSI-D3P: R285.2 UU1.B3(PD11/LCD_D15/I2S1_BCLK/DSI_D3P)
MIPI-RESET: C21.2 CON1.5(RESET) D2.1 R14.2
MIPI_DSI-CKN: CON1.11(MIPI_LKN) R278.1
MIPI_DSI-CKP: CON1.10(MIPI_LKP) R277.1
MIPI_DSI-D0N: CON1.14(MIPI_D0N) R282.1
MIPI_DSI-D0P: CON1.13(MIPI_D0P) R281.1
MIPI_DSI-D1N: CON1.17(MIPI_D1N) R280.1
MIPI_DSI-D1P: CON1.16(MIPI_D1P) R279.1
MIPI_DSI-D2N: CON1.20(MIPI_D2N) R276.1
MIPI_DSI-D2P: CON1.19(MIPI_D2P) R283.1
MIPI_DSI-D3N: CON1.23(MIPI_D3N) R284.1
MIPI_DSI-D3P: CON1.22(MIPI_D3P) R285.1
MIPILCD-RST: D2.2 RL13.2
MODLE_EN: Q12.1(B) Q13.3(C) R271.2 U17.5(EN)
NET_STATUS: Q11.1(G) R263.1
PHY-AVDD33: CM4.2 CM5.2 CM13.2 R92.2 R93.2 R243.2 RM2.2 RM10.1 RM16.2 RM17.1 RM22.1 RM24.1 RM29.1 U8.13(DVDD33_IO) U8.31(AVDD33)
PLLTEST: R4.2 R7.2 UU1.K8(PLLTEST)
PMU-BLDO1: CP19.2 RP117.2 UP1.12(BLDO1)
PMU-SCK: RP5.2 UP1.40(SCK) ; also on sheet 14
PMU-SDA: RP4.2 UP1.39(SDA) ; also on sheet 14
PS: CN2.1 CP2.1 CP3.2 CP10.1 CP11.2 D1.2 RL1.1 RP33.1 RP87.2 UP1.6(VIN3) UP1.7(VIN4) UP1.17(ALDOIN) UP1.23(VIN1) UP1.24(VIN2) UP1.34(VSYS) UP1.36(VMID)
PWRKEY: R262.2 U15.74(PWRKEY)
PWRON-AXP2101: CP30.2 RP8.1 RP23.2
REGOUT: CM14.1 CM15.1 U8.28(REGOUT)
RESET_N: C109.2 Q10.3(C) U15.75(RESET_N)
RMII-CRS_DV: R98.1 ; also on sheet 14
RMII-MDC: R103.1 ; also on sheet 14
RMII-MDI0+: RJ2.1(TD+) U8.30(MDI_TP) U9.4 U9.5
RMII-MDI0-: RJ2.2(TD-) U8.29(MDI_TN) U9.3 U9.6
RMII-MDI1+: RJ2.3(RD+) U8.27(MDI_RP) U9.2 U9.7
RMII-MDI1-: RJ2.6(RD-) U8.26(MDI_RN) U9.1 U9.8
RMII-MDIO: R104.1 ; also on sheet 14
RMII-RESET: CM17.2 RM29.2 U8.32(RESET_N) ; also on sheet 14
RMII-RXD0: R97.1 ; also on sheet 14
RMII-RXD1: R96.1 ; also on sheet 14
RMII-RXER: R99.1 ; also on sheet 14
RMII-TXCK: RM27.1 U8.10(TXCLK/50M_CLKI) ; also on sheet 14
RMII-TXD0: R101.1 ; also on sheet 14
RMII-TXD1: R100.1 ; also on sheet 14
RMII-TXEN: R102.1 ; also on sheet 14
RMII-XTAL1: RM28.1 U8.2(X1)
RMII_CRS_DV: R98.2 RM26.1 U8.19(RXDV/TPN_FIBER)
RMII_MDC: R103.2 U8.22(MDC)
RMII_MDIO: R104.2 RM2.1 U8.23(MDIO)
RMII_RXD0: R97.2 U8.18(RXD0)
RMII_RXD1: R96.2 U8.17(RXD1)
RMII_RXER: R99.2 RM16.1 U8.21(RXER/INTR_32)
RMII_TXD0: R101.2 U8.9(TXD0)
RMII_TXD1: R100.2 U8.8(TXD1)
RMII_TXEN: R102.2 U8.5(TXEN)
RS485_A_1: D12.4(AC_IN_1) J9.1 R247.2 R248.1 U11.12(A)
RS485_A_2: D15.4(AC_IN_1) J10.1 R254.2 R255.1 U13.12(A)
RS485_B_1: D12.3(AC_IN_2) J9.2 R248.2 R249.1 U11.13(B)
RS485_B_2: D15.3(AC_IN_2) J10.2 R255.2 R256.1 U13.13(B)
RS485_CTRL1: R250.1 U11.4(~{RE}) U11.5(DE) ; also on sheet 14
RS485_CTRL2: R257.1 U13.4(~{RE}) U13.5(DE) ; also on sheet 14
RST_WIR: Q10.1(B) ; also on sheet 14
RX-CLK: CM18.2 RM27.2 U8.14(RX_CLK/50M_O)
SA0: UD1.N3(A0) UU1.AA19(SA8)
SA1: UD1.P7(A1) UU1.AB16(SCAS)
SA2: UD1.P3(A2) UU1.W20(SA5)
SA3: UD1.N2(A3) UU1.Y19(SA2)
SA4: UD1.P8(A4) UU1.AC17(SA0)
SA5: UD1.P2(A5) UU1.AB22(SA14)
SA6: UD1.R8(A6) UU1.AB17(SBA0)
SA7: UD1.R2(A7) UU1.AA22(SA15)
SA8: UD1.T8(A8) UU1.AB18(SBA1)
SA9: UD1.R3(A9) UU1.U19(SA9)
SA10: UD1.L7(A10) UU1.AC13(SRAS)
SA11: UD1.R7(A11) UU1.AC19(SA4)
SA12: UD1.N7(A12) UU1.AC20(SA6)
SA13: UD1.T3(A13) UU1.W21(SA7)
SA14: UD1.T7(A14) UU1.AB19(SA3)
SA15: UD1.M7(A15) UU1.AB21(SA13)
SBA0: UD1.M2(BA0) UU1.W19(SA12)
SBA1: UD1.N8(BA1) UU1.AB15(SWE)
SBA2: UD1.M3(BA2) UU1.Y17(SA1)
SCAS: UD1.K3(CAS#) UU1.AA15(SBA2)
SCKE0: UD1.K9(CKE0) UU1.AB11(SCKE0)
SCKE1: UD1.J9(CKE1) UU1.AB12(SCKE1)
SCKN: RD6.2 UD1.K7(CK#) UU1.V15(SCKN)
SCKP: RD6.1 UD1.J7(CK) UU1.W15(SCKP)
SCS0: UD1.L2(CS0#) UU1.AA17(SCS0)
SCS1: UD1.L1(CS1#) UU1.AB13(SCS1)
SDQ0: UD1.H7(DQL7) UU1.AC10(SDQ0)
SDQ1: UD1.H8(DQL5) UU1.AC11(SDQ1)
SDQ2: UD1.G2(DQL6) UU1.Y13(SDQ2)
SDQ3: UD1.H3(DQL4) UU1.AA13(SDQ3)
SDQ4: UD1.E3(DQL0) UU1.AA11(SDQ4)
SDQ5: UD1.F2(DQL2) UU1.W13(SDQ5)
SDQ6: UD1.F8(DQL3) UU1.AB9(SDQ6)
SDQ7: UD1.F7(DQL1) UU1.AB8(SDQ7)
SDQ8: UD1.A3(DQU7) UU1.AC5(SDQ8)
SDQ9: UD1.C3(DQU1) UU1.AB6(SDQ9)
SDQ10: UD1.A7(DQU4) UU1.W7(SDQ10)
SDQ11: UD1.B8(DQU6) UU1.AA7(SDQ11)
SDQ12: UD1.D7(DQU0) UU1.W9(SDQ12)
SDQ13: UD1.C8(DQU2) UU1.Y9(SDQ13)
SDQ14: UD1.A2(DQU5) UU1.AC4(SDQ14)
SDQ15: UD1.C2(DQU3) UU1.AB5(SDQ15)
SDQM0: UD1.E7(DML) UU1.AA9(SDQM0)
SDQM1: UD1.D3(DMU) UU1.AB7(SDQM1)
SDQS0N: UD1.G3(DQSL#) UU1.V11(SDQS0N)
SDQS0P: UD1.F3(DQSL) UU1.W11(SDQS0P)
SDQS1N: UD1.B7(DQSU#) UU1.AC8(SDQS1N)
SDQS1P: UD1.C7(DQSU) UU1.AC7(SDQS1P)
SIM_CLK: R268.2 U15.5(USIM_CLK)
SIM_DATA: R269.2 U15.6(USIM_DATA)
SIM_DET: R264.1 U15.9(USIM_DET) U16.CD
SIM_RST: R267.2 U15.7(USIM_RST)
SIM_VCC: C120.1 E5.1 R265.2 U15.8(USIM_VDD) U16.C1(VCC)
SODT0: UD1.K1(ODT0) UU1.AC14(SODT0)
SODT1: UD1.J1(ODT1) UU1.AC16(SODT1)
SRAS: UD1.J3(RAS#) UU1.AC22(SA11)
SRST: UD1.T2(RESET) UU1.AB23(SRST)
SVREF: CD16.1 RD4.2 RD5.1 UD1.H1(VREFDQ) UD1.M8(VREFCA) UU1.V7(SVREF)
SWE: UD1.L3(WE) UU1.W17(SA10)
TEST: TP197.1(TP) UU1.N6(TEST)
TEST_ON: RM17.2 RM21.1 U8.24(TEST_ON)
TS: BATT1.2 RP2.1 UP1.31(TS)
TWI-A-SCK: CON4.7(SCK1) R22.1 UU1.E17(PA14/NCSI_D2/TWI1_SCK/CLK_FANOUT0)
TWI-A_SDA: CON4.8(SDA1) R23.1 UU1.D17(PA15/NCSI_D3/TWI1_SDA/CLK_FANOUT1)
TWI-B-SCK: CON4.33(SCK0) R142.1 UU1.F15(PA16/NCSI_D4/TWI0_SCK/UART3_TX)
TWI-B-SDA: CON4.34(SDA0) R143.1 UU1.E15(PA17/NCSI_D5/TWI0_SDA/UART3_RX)
UART1_RX: U13.3(R_RXD) ; also on sheet 14
UART1_TX: U13.6(D_TXD) ; also on sheet 14
UART3_RX: U11.3(R_RXD) ; also on sheet 14
UART3_TX: U11.6(D_TXD) ; also on sheet 14
UIM_CLK: C123.2 E3.1 R268.1 U16.C3(CLK)
UIM_DATA: C121.2 E2.1 R265.1 R269.1 U16.C7(IO)
UIM_RESET: C122.2 E4.1 R267.1 U16.C2(RST)
USB0-DM: UU1.A13(USB0_DM) ; also on sheet 13
USB0-DP: UU1.B13(USB0_DP) ; also on sheet 13
USB1_DM: U15.27(USB_DM) ; also on sheet 13
USB1_DP: U15.26(USB_DP) ; also on sheet 13
USB_BOOT: J11.2 U15.55(NET_STATUS/USB_BOOT)
USB_VBUS: D19.3(D) U15.28(USB_VBUS)
VLED+: CL3.1 CL4.1 CON1.8(LED+) DL1.2 UL1.5(VOUT)
VLED-: CON1.7(LED-) RL3.2 RL5.1 RL6.1
VRA1: C36.2 UU1.J20(VRA1)
VRA2: C33.2 UU1.J21(VRA2)
X32KIN: C12.2 R5.2 UU1.K2(X32KIN) X1.2
X32KOUT: C14.2 R5.1 UU1.J2(X32KOUT) X1.1
N16971193: J11.1 R259.1
N16979710: C106.2 U15.48(MAIN_DCD)
N16998260: C107.2 J12.1 R260.2
N17093888: C124.1 L6.1 U17.2(SW)
N17093951: C129.2 R272.1 R275.2 U17.4(FB)
N17863524: C15.2 R6.2 Y1.3(XOUT)
N19547422: RD3.1 UU1.Y5(SZQ)
N19776917: C5.2 R240.2 UU1.J5(VCC_RTC)
N19815648: RD1.1 UD1.L8(ZQ0)
N19914347: DP1.1 RP87.1
N19914584: LP5.1 UP1.8(LX4)
N19914616: LP4.1 UP1.5(LX3)
N19914668: LP1.2 UP1.35(SW)
N19914824: CP9.2 UP1.2(VREF)
N19914859: CP24.2 RP8.2 UP1.30(PWRON)
N19915188: CP4.2 CP31.2 LP2.2 RP81.1 UP1.21(FB1)
N19915248: LP2.1 UP1.22(LX1)
N19993640: RD8.1 UD1.L9(ZQ1)
N20020632: TP188.1(TP) UU1.L5(PWR_ON)
N20020662: TP189.1(TP) UU1.J4(PWR_STARTUP)
N20020664: TP190.1(TP) UU1.G4(PWR_EN0)
N20020666: TP191.1(TP) UU1.E3(PWR_EN1)
N20020668: TP192.1(TP) UU1.L3(PWR_EN2)
N20020677: R2.2 UU1.J3(PWR_BYP)
N20148257: RD7.1 UU1.U18(DDR3_SZQ1)
N20761652: RL13.1 UU1.C5(PD19/LCD_DE/PWM9/TCON_TRIG/SPI2_MOSI)
N20761656: RL14.1 UU1.D9(PD20/LCD_HSYNC/PWM10/MDC/SPI2_MISO)
N20819248: C80.2 RS1.2 RS3.1 US1.2(EN)
N20819266: CS1.1 US1.6(BS)
N20819277: CS1.2 LS1.1 US1.5(LX)
N20819283: CS3.2 RS2.1 RS4.1 US1.1(FB)
N20819293: CP25.2 CP26.2 CS3.1 LS1.2 RS2.2 RS5.1 RS6.1
N20824804: C84.2 EC1.1 Q2.3(DRAIN) R84.2 R86.2 R87.2
N20824824: EC1.2 EC2.1 R87.1 R89.2
N20824838: D3.2(K) R84.1 R86.1
N20824911: C83.2 Q2.2(SOURCE) R85.1
N20830721: RM3.2 U8.25(ISET)
N20917643: K10.1 RP22.1
N20917672: K9.1 RP23.1
N21070970: DP3.1 RP25.1
N21073206: Q13.1(B) R273.2 R274.1
N21073244: D19.1(G) Q12.3(C) R270.2
N21089015: D18.2(CATHODE) Q11.3(D)
N21147056: CN2.2 R43.1
N21147059: CN2.3 R45.1
N21270291: CON1.1(LCM_ID2) R165.1 R166.1
N21357732: D12.1(DC_OUT_PLUS) D13.2(CATHODE)
N21357734: D12.2(DC_OUT_MINUS) D14.1(ANODE)
N21365100: D11.2 F2.1
N21365102: F2.2 M1.1 T1.2(IN2)
N21365112: J3.2 M1.2 T1.3(OUT2)
N21365116: D11.1 J3.1
N21373320: C86.1 RJ2.5(RCT)
N21375300: R93.1 RJ2.9(GA)
N21375578: C87.2 RJ2.4(TCT)
N21375931: R94.1 RJ2.12(YA)
N21376357: C89.1 RJ2.13(GND1) RJ2.14(GND2)
N21377840: C92.1 RJ1.5(RCT)
N21377929: R243.1 RJ1.9(GA)
N21377931: C91.2 RJ1.4(TCT)
N21377936: R241.1 RJ1.12(YA)
N21377953: C93.1 RJ1.13(GND1) RJ1.14(GND2)
N21379417: L2.2 U12.2(VIN)
N21379418: L3.1 U12.4(+VO)
N21379703: D15.2(DC_OUT_MINUS) D17.1(ANODE)
N21379705: D15.1(DC_OUT_PLUS) D16.2(CATHODE)
N21380589: L5.1 U14.4(+VO)
N21380590: L4.2 U14.2(VIN)
N21397136: R95.1 RJ2.11(YK)
N21397139: R242.1 RJ1.11(YK)
N21419886: CL1.1 CL2.1 LL1.1 RL1.2 UL1.6(VIN)
N21419940: CL5.1 RL2.2 RL4.1 UL1.4(EN)
N21420093: DL1.1 LL1.2 UL1.1(LX)
N21423029: RL3.1 UL1.3(FB)
N21423487: C124.2 U17.6(BOOT)
N21423526: D18.1(ANODE) R261.2

Not connected (* = marked no-connect by the designer): CON1 6(LPTE); CON4 11(DGND4)*; K1 3; K9 3; K10 3; RJ1 7(NC)*; RJ2 7(NC)*; U2 4(FB)*; U8 1(TXER/FXSD)* 3(X2)* 6(TXD3)* 7(TXD2)* 15(RXD3)* 16(RXD2)*; U11 11(NC1)* 14(NC2)*; U13 11(NC1)* 14(NC2)*; U15 1(RESERVED1)* 2(RESERVED2)* 3(RESERVED3)* 4(RESERVED4)* 10(RESERVED5)* 11(RESERVED6)* 12(RESERVED7)* 13(RESERVED8)* 14(RESERVED9)* 15(RESERVED10)* 16(RESERVED11)* 17(RESERVED12)* 19(ADC)* 20(RESERVED13)* 21(SPK_N) 22(SPK_P)* 23(MIC_N)* 24(MIC_P)* 25(MIC_BIAS) 31(MAIN_RXD) 32(MAIN_TXD) 33(MAIN_CTS)* 34(MAIN_RTS)* 39(MAIN_DTR)* 40(MAIN_RI)* 41(RESERVED14)* 42(RESERVED15)* 49(WAKEUP_IN) 50(AP_READY) 51(W_DISABLE#) 52(NET_MODE) 53(SLEEP_IND) 56(I2C_SDA)* 57(I2C_SCL)* 58(PCM_SYNC)* 59(PCM_DIN)* 60(PCM_DOUT)* 61(PCM_CLK)* 62(RESERVED16)* 63(RESERVED17)* 64(RESERVED18)* 65(RESERVED19)* 66(RESERVED20)* 67(RESERVED21)* 68(RESERVED22)* 69(RESERVED23)* 70(RESERVED24)*; U16 C6(VPP)*; UP1 25(LX2)* 26(FB2)*; UU1 A2(PD18/LCD_CLK/EPHY_25M/SPI2_CLK)* B9(PD0/LCD_D2) C7(PD12/LCD_D18/I2S1_LRCK/DMIC_DATA3/PWM11)* C9(PD8/LCD_D12/PWM7/RMII_TXEN)* D5(PD17/LCD_D23/I2S1_DIN0)* E4(PD15/LCD_D21/I2S1_DOUT2/I2S1_DIN2/DMIC_DATA0)* E5(PD21/LCD_VSYNC/MDIO/SPI2_CS0) E7(PD16/LCD_D22/I2S1_DOUT3/I2S1_DIN3/DMIC_CLK)* H2(REFCLK_OUT)* H22(MICIN1N) J22(MICIN1P) K23(MICIN2N) L22(LINEOUTP) L23(MICIN2P) M22(LINEOUTN) N20(GPADC0)

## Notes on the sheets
sheet 1
- REVISION HISTORY
- Revision
- Description
- Date
- Drawn
- Checked
- Schematics Index：
- Ver 0.1
- Initial Version
- 2022-11-29
- QIAO
- P01: REVISION HISTORY
  P02: BLOCK
  P03: POWER TREE
  P04: GPIO ASSIGNMENT
  P05: POWER
  P06: CPU
  P07: JTAG/DEBUG
  P08: DDR3_16X1
  P09: eMMC/BOOTSEL
  P10: MIPI LCD
  P11: MIPI CSI
  P12: CARD/USB
  P13: RS485
  P14: RMII
  P15:4G
sheet 2
- BLOCK
- 32.768KHz
- 24MHz
- DDR/Flash
- RTC
- DCXO
- DDR3/DDR3L 16X1
- DRAMC
- EMAC/GMAC
- IP101
- RMII1
- RMII
- SMHC
- EMMC
- Ephy
- RMII2
- TF_CARD
- SDC3.0
- MIPI_LCD
- LCD
- USB
- MIPI
- USB ID
- USB ID
- OTG
- Micro_USB
- MIPI_CSI
- CAREMA
- FSUSB42MUX
- USB2.0
- HOST
- 4G CAT1
- UART1
- ISO3082DWR
- RS485X1
- TDI/TMS/TCK..
- JTAG
- UART3
- RS485X2
- Analysis
- DEBUG
- UART0
- RS485
- RST
- BOOT
- BOOT SEL
- Download
sheet 3
- DEFAULT POWER ON
- POWER TREE
- DEFAULT POWER OFF
- AXP2101
- DCDC5
- 1.2V AHD-1V2/DVDD-CSI(OFF)
- BACKLIGHT
- BAT
- VSYS
- AUDIO AMP
- VCC-IO/VCC33-USB/VCC33-PF/VCC-PD/
  VCC-PC/VCC-PE/VCC-PG
  /VCC-CARD/VCC33-WIFI/VCC-EPHY/
  VCC-LCD/VCC-CTP(ON)
- 1.5V-3.4V/2A
- VCC-PC/VCC-PE/VCC-PG 开发板默认为3.3V
- DC/DC1
- VCC-PA/PI开发板默认为1.8V
- DC12V
- 400mΩ from DCDC1
- DC1SW/DLDO1
- 3.3V VCC-LCD/CTP(OFF)
- 12V/1A
- 0.5V-1.2V/2A
- DCIN
- DC/DC2
- 0.9V  (ON)
- 5V/2A
- Battery
  Charger
  &
  Power
  Detect
- 0.5V-1.2V/2A
- VBUS
- DC/DC3
- 0.9V VDD-SYS/VDD09-USB(ON)
- 0.5V-1.84V/1A
- DC/DC4
- 1.35V/1.5V VCC-DRAM(ON)
- 3.5-4.2V
- BAT
- DC4LDO
- 0.5V-1.4V/30mA
- 0.9V VDD09-USB(ON)
- VDD09-USB for usb standby
- 0.5V-1.4V/300mA
- DC4SW/DLDO2
- 1.2V DVDD-CSI(OFF)
- 0.7-3.3V/200mA
- ALDO1
- 1.8V (ON)
- AVCC 默认使用内部LDO输出
- 0.7V-3.3V/200mA
- ALDO2
- 1.8V (OFF)
- PS
- 0.7V-3.3V/200mA
- ALDO3
- 3.3V VCC-PI(ON)
- PI口供电外挂一个LDO转1.8V(开发板）
- VCC33-USB for usb standby
- 0.7V-3.3V/200mA
- ALDO4
- 3.3V (OFF)
- 1.8V/300mA
- 1.8V VDD18-DRAM/VCC-PLL/VCC18-PF/VCC18-MDSI/
  VCC18-MCSI/VCC-PA/VCC-PC/PE/PG(ON)
- PS
  DCDC1
- BLDO1
- BLDO2
- 2.8V/300mA
- 2.8V AVDD-CSI(OFF)
- 1.8V/30mA
- VCC-RTC
- 1.8V VCC-RTC(ALWAYS ON)
- 1.8V VCC-SENSORE(ON)
- highPSRR-LDO
- 2.8V/300mA
- 2.8V AVDD-CSI(OFF)
sheet 4
- GPIO ASSIGNMENT
- 1.   RS485_CTRL1   :    AB2
- 2.   RS485_CTRL2   :    W3
- 3.   RST_WIR   :            W4
- 4.   CAT_ON   :              W5
- 5.   CARD-PWROFF   :  V22
sheet 5
- VBAT&SUPER CAP
- BATT
- Pwr in
- 2A 保险丝
- 当接入输入电源ACINVGS>0 ,MOSFET 截止，输入电源ACIN 通过体二极管给电池充电。
- 3.75V
- BAT 3.6~4.2V
- 5V
- 0.45V
- 4.6V
- 体二极管=0.75V
- d
- s
- 18V 压敏电阻
- g
- EC1
- 40V 3A
- 5V
- 550mV
- 12V
- EC2
- 1.3kΩ@100MHz 2.5A
- 12V BUCK
- 20mA
- 1.8V
- 初始化1.1V,后续调节输出1.35v
- 1.35/1.5V
- 600mA
- 内存DDR供电
- 20mA
- 3.3V
- 1.8V(ON)
- 1.8V
- 2A
- 5V@3A
- 20mA
- 3.3V
- 3.3V
- 20mA
- 1.8V(ON)
- 内存DDR控制器
- 20mA
- RA
- 3.3V
- 20mA
- RB
- 20mA
- 1.8V
- Vout = 0.6 x (1 + RA/RB)
  Imax = 5A
- 12V-5V
- 20mA
- 1.8V
- 20mA
- PLL
- 1.8V
- 20mA
- 3.3V
- 150mA
- 内部LDOA-1.8V 输出
- 0.9V
- 1A
- 0.9V
- Power Supply for System
- 20mA
- MIPI CSI Power
- AXP2101
- 5V@2A
- 3.3V
- IMAX=2A
- 20mA
- MIPI DSI Power
- 外设
- 3.3V
- 2.8V
- 20mA
- 1.2V@ 1000mA
- Flash
- 200mA
- 需求较高时需外挂high PSRR LDO
- 3.3V
- 带载能力弱
- 1.2v
- 150mA
- 150mA
- phy
- 1.2v
- SD
- 20mA
- Camera
- 100mA
- 0.9V
- WIFI
- IMAX=1.5A
- 20mA
- IMAX=0.3A
- 1.8V
- 2.8V
- IMAX=0.3A
- IMAX=0.3A
- 3.3V
- LCD
- 50mA
- 3.3 V Digital
- 2.9V
- 3.3V
- 1.1V
- IMAX=1A
- 20mA
- USB Analog Power
- IMAX=0.3A
- 1.8V
- 0.9V
- GPS
- 20mA
- IMAX=0.3A
- 2.8V
- 1.2V
- CDR 此路用GPS
- USB STANDBY用此路供电
- USB Digital Power
- 注意DLDO2输入源为DCDC4,
  输入电压要高于1.2V时 才可设置为LDO 输出
- 输出能力弱
- Just for Leakage Test
- 0.9V
- 1.8V
- 20mA
- 20mA
- 20mA
- 1.8V(OFF)
- 20mA
- 20mA
- 20mA
- 20mA
- 3.3V(ON)
- 20mA
- 20mA
- 20mA
- NC
- AVCC 用内部ALDO供电
- USB STANDBY用此路供电
- For 3g
sheet 6
- 不使用
- 内部LDOA-1.8V 输出
- Imax=1.5A
- FOR TEST
- 注意FEL 上拉电源为VCC-IO 3.3V
  不能直接接GPADC(1.8V)
- Away from the board outline
  and senstive signal.
  Around GND line.
  Routing in Power Layer.
- Close to AP
- 上电低电平进入烧写模式
- 信号远离板边以及干扰信号，
  做包地处理
- DCXO-24Mhz
- TEST 测试点就近放置于TOP层
- PCB上注意用大号字体标注,放置于板边
- 1: 软件可选择从JTAG功能从PF（Default ）或PB口出
  0: Force JTAG功能从PB口出
- PMC 模块功能由PWR-BYP决定，配置说明如下：
- 1.PMC 功能PIN有效；
  2.上电内部复位有效（需要外接高电平）；
  3.工作时支持外部复位PMC来复位SOC；
- RESET-BYP
- 浮空为高电平
- 1.PMC 功能PIN无效；只有NMI/RESET信号有效；
  2.上电内部复位有效；也可外接PMU PWROK信号复位；
  3.工作时支持外部复位；
- 接地为低电平
- 使用全志物料24MHz-E3SB24E004304E
- 32.768KHz
- connect oscilloscope probe
- PLL-TEST
- 32K改用贴片32K物料
- AVCC 为内部LDO供电
- SCREW HOLES
- Audio Codec
- 放在芯片下方
- 预留测试
- DECOUPLE CAP
sheet 7
- DDR3 16X1
- For two DIE
- 默认使用外部电阻
- 1A
- SIP 封装需要贴片
- 20mA
- 默认使用内部SVREF
- Placed on bottom
sheet 8
- LCD/PWM
- Differential pairs Z0= 100 ohm
- CTP CN
- 触摸屏
- MIPI LCD
- IR_Cut
- MIPI-LCD BL:6S2P
- BACKLIGHT
- PWM_Frequence=50KHz
- R=200mV/I(led)
sheet 9
- 1.2V
- 2.8V
- 1.8V
- MIPI CSI
- IO
- 两组MIPI-2lane
- MIPI-4lane
- PA0
- MIPIA-CSI-CK0P
- MIPI-CSI-CKP
- PA1
- MIPIA-CSI-CK0N
- MIPI-CSI-CKN
- PA2
- MIPIA-CSI-D1N
- MIPI-CSI-D1N
- PA3
- MIPIA-CSI-D1P
- MIPI-CSI-D1P
- PA4
- MIPIA-CSI-D0P
- MIPI-CSI-D0P
- PA5
- MIPIA-CSI-D0N
- MIPI-CSI-D0N
- PA6
- MIPIB-CSI-D0N
- MIPI-CSI-D2N
- PA7
- MIPIB-CSI-D0P
- MIPI-CSI-D2P
- PA8
- MIPIB-CSI-D1N
- MIPI-CSI-D3N
- PA9
- MIPIB-CSI-D1P
- MIPI-CSI-D3P
- PA10
- PA11
- MIPIB-CSI-CK0N
- MIPIB-CSI-CK0P
sheet 10
- interface
sheet 11
- Imax=300mA
- RMII
- NOTE:CLOSE TO pin14
- phy address
- U8 pin14输出50MHz
- TXC(REF_CLK)
- PHY 时钟输出同步至v853
- TX
- E_PHY_AD0
- E_PHY_AD0
- E_PHY_AD3
- 0
- 1
- 增加RM13方便走线
- E_PHY_AD3
- CONFIG
- PULL HIGH
- Pull down
- RX
- TEST
- TEST mode
- Normal mode
- COL/RMII
- RMII mode
- MII mode
- Mpu 时钟输出25M-->phy
- CRS
- LED mode1
- LED mode0
- RX_DV
- -
- option
- Normal mode
- NOTE:The XTAL1 needs to be connected to GND.
  if the external 25MHz clock used.
- RMII mode
- LED mode0
- MDC
- option
- Ephy
sheet 12
- 复位控制
- 模组复位
- 470uF,10V
- 指示灯
- HIGH 关闭
- Vout=0.596x(1+R1/R2)
- SIM_CARD
- Cat1 电源输入
